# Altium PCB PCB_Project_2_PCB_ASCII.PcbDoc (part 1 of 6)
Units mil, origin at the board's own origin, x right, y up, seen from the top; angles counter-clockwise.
Board outline 3900 x 7800 mil, 6 copper layers (Top Layer, GND 1, Signal, Power, GND 2, Bottom Layer), stack 62.1 mil thick; 636 components, 334 nets, 1830 pads, 1401 vias.
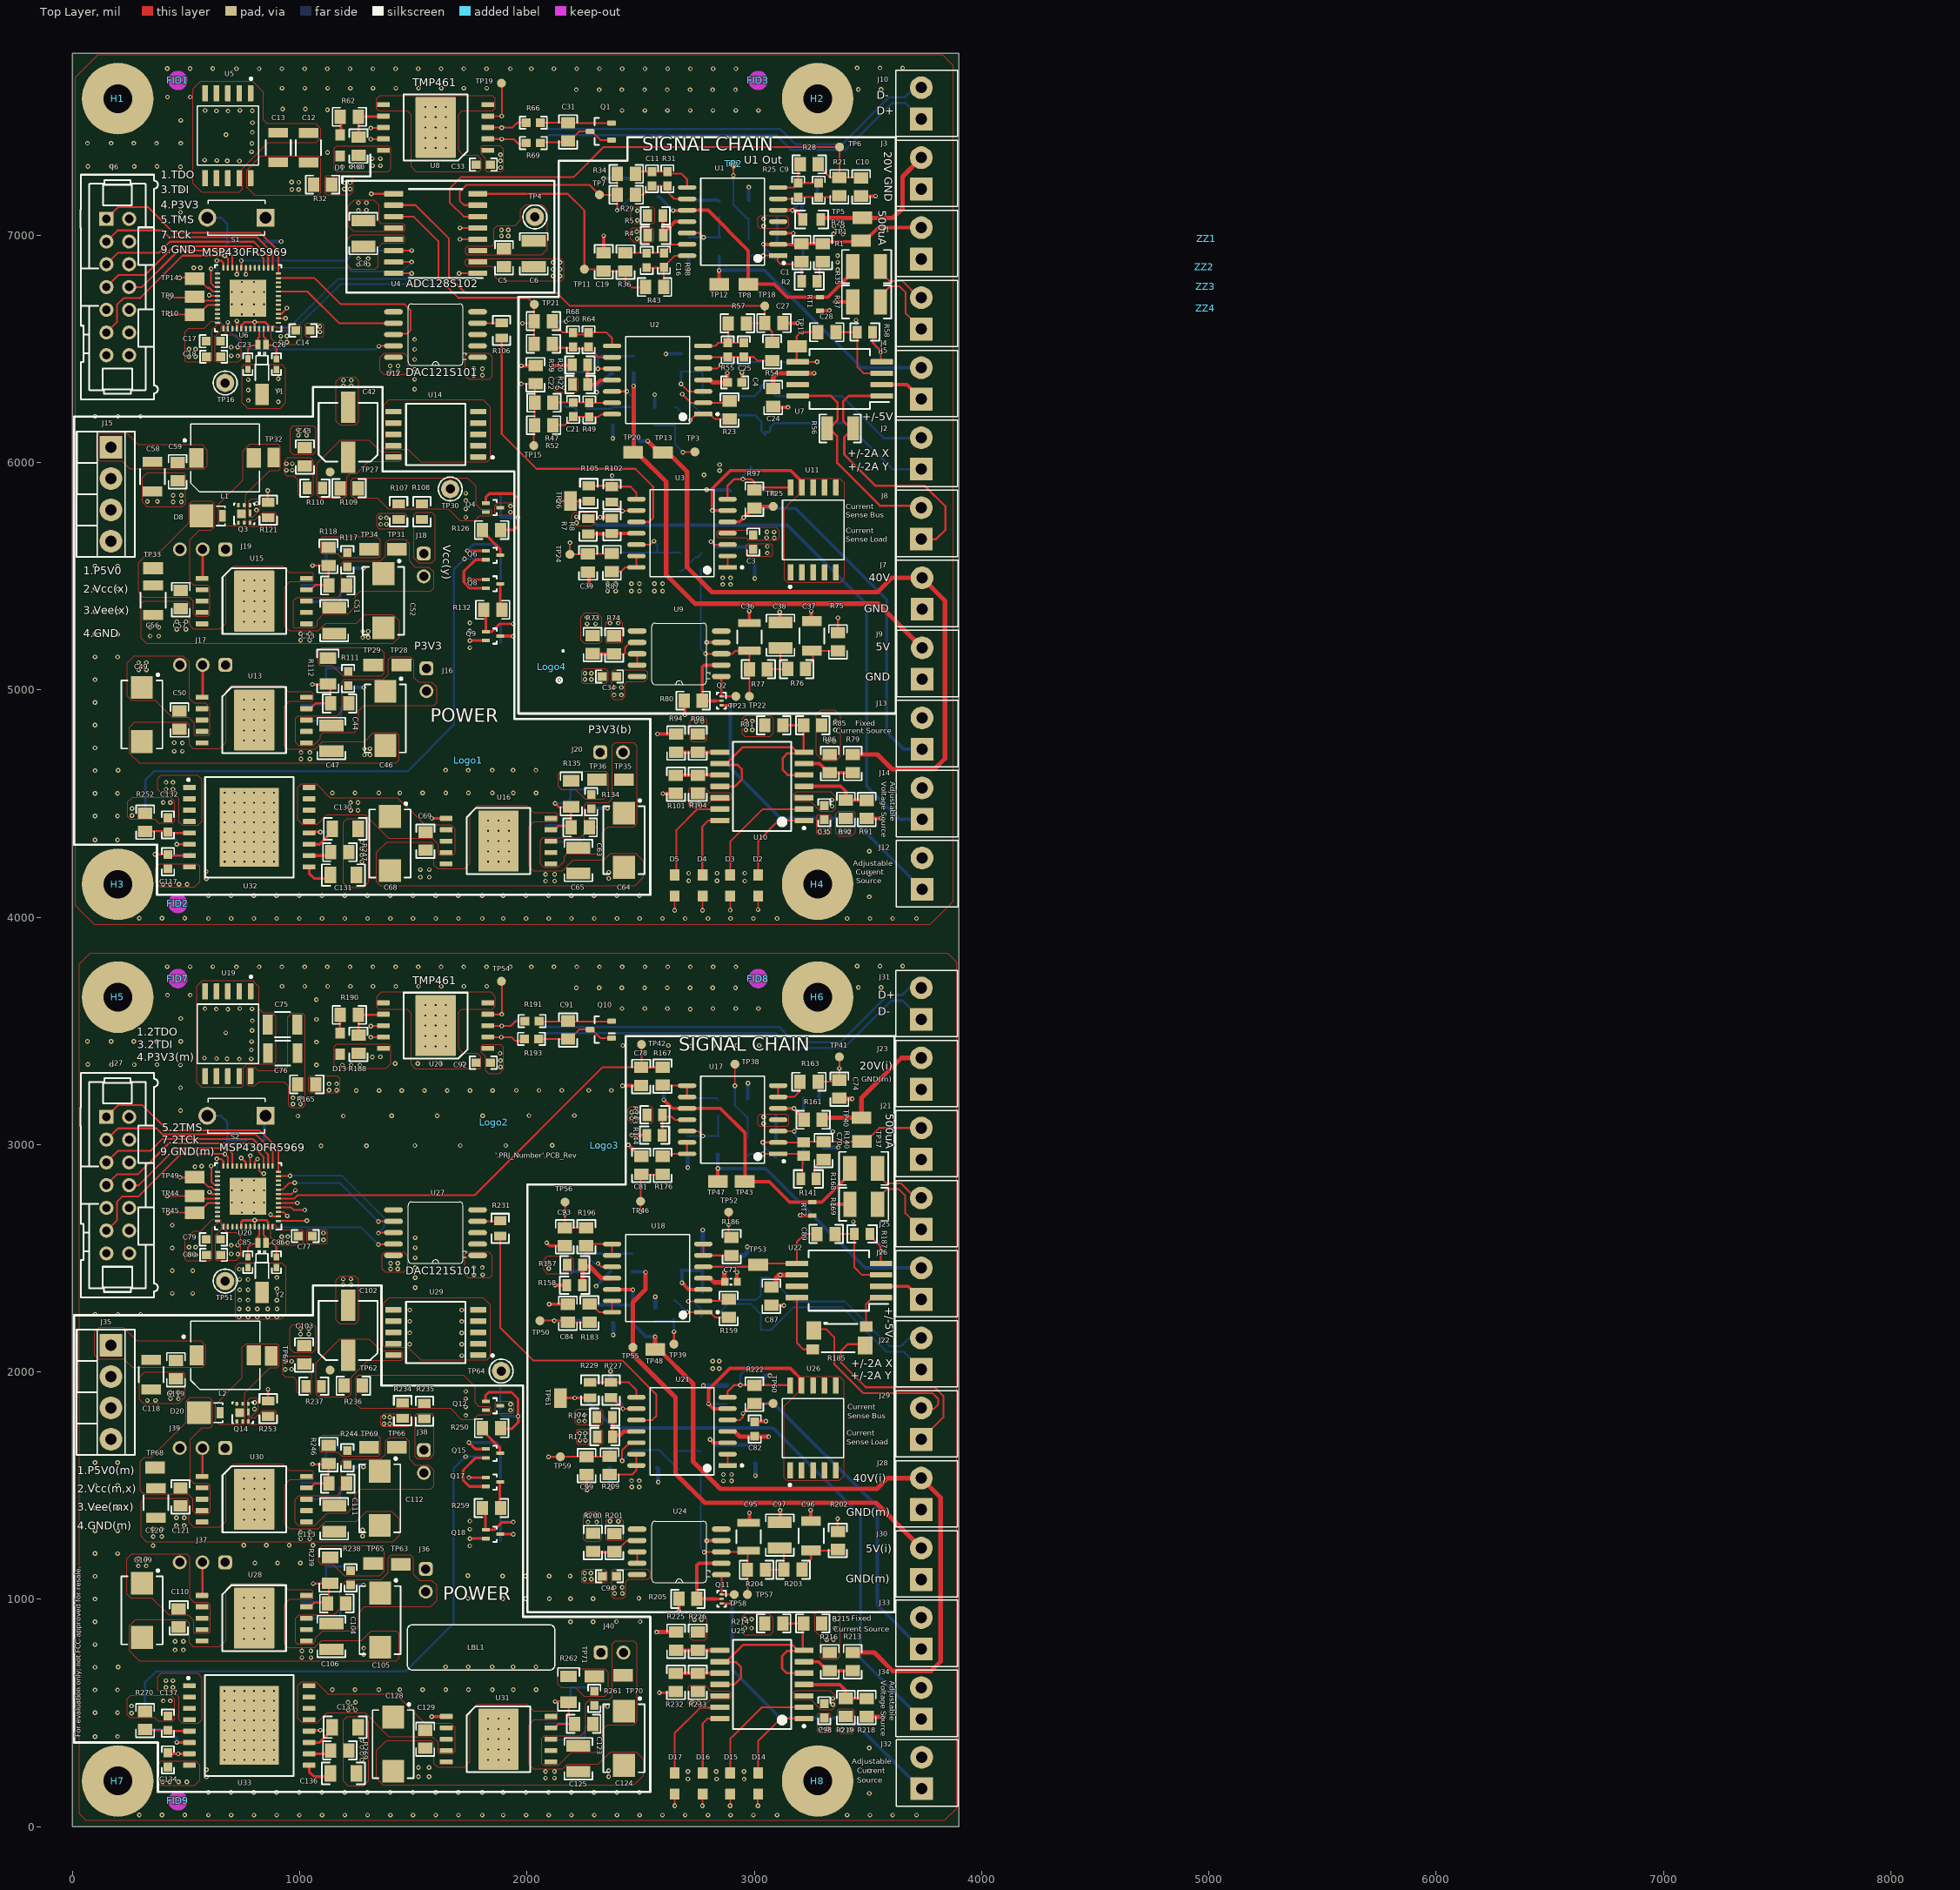
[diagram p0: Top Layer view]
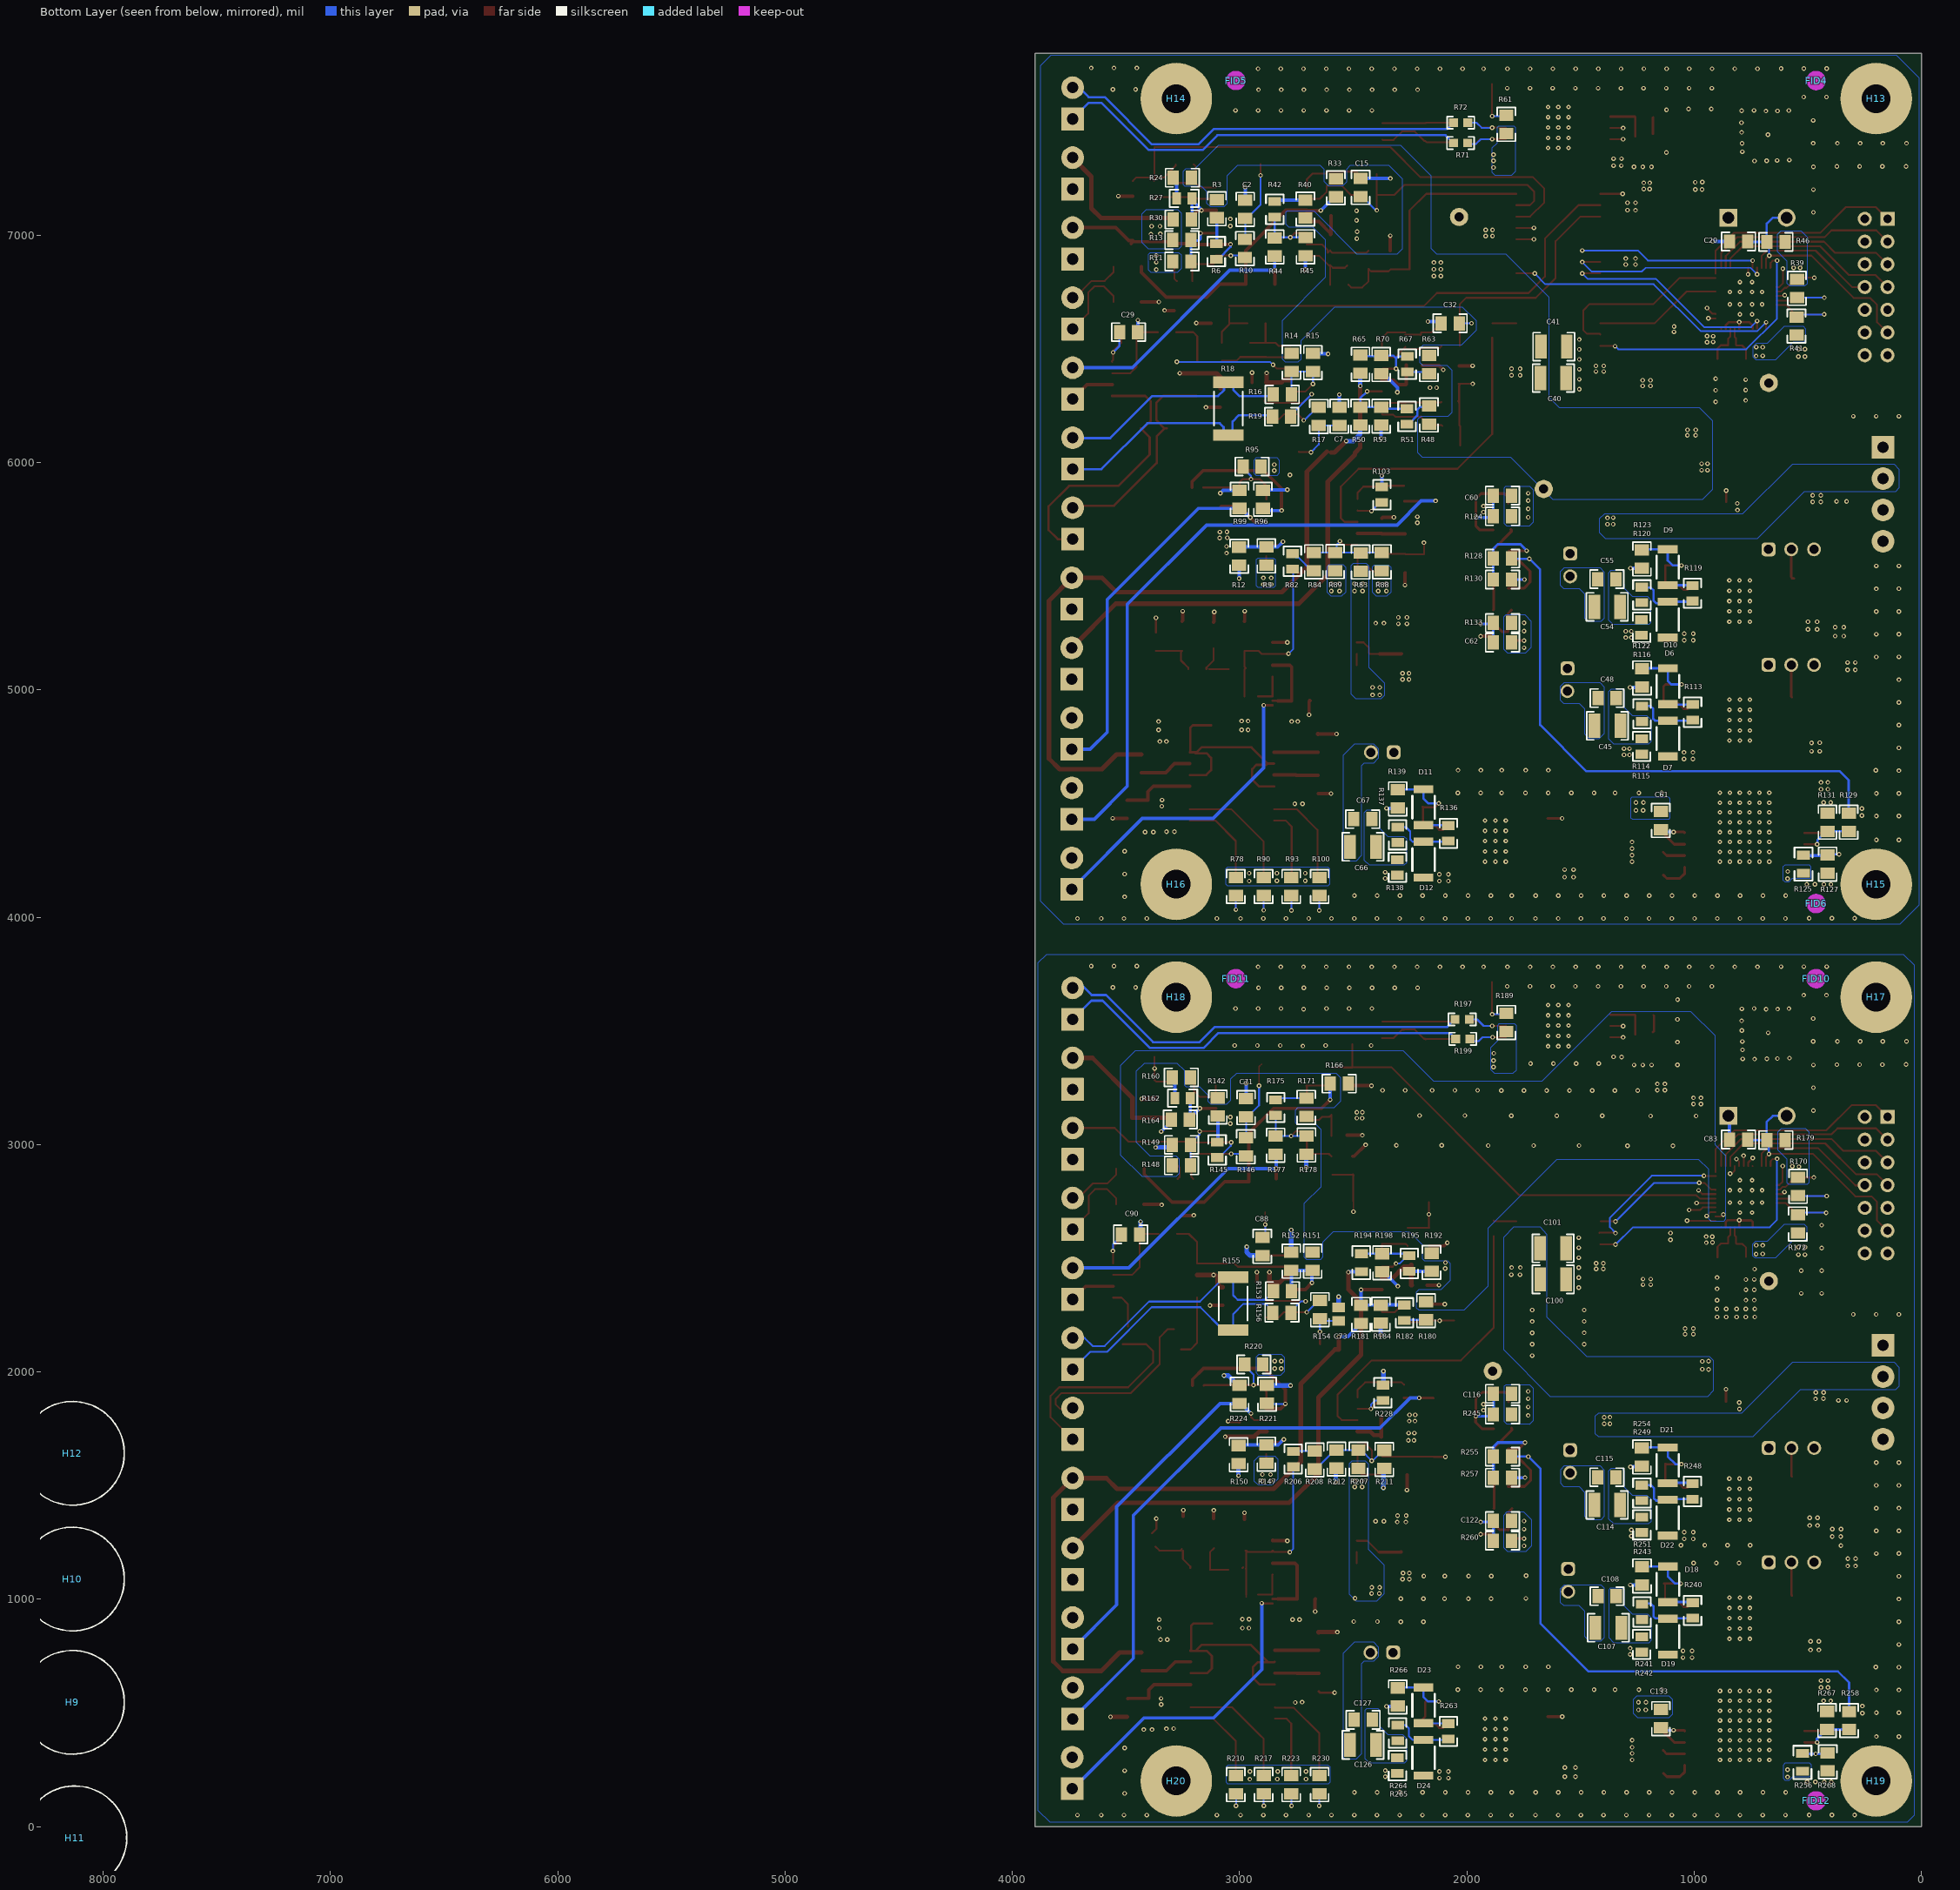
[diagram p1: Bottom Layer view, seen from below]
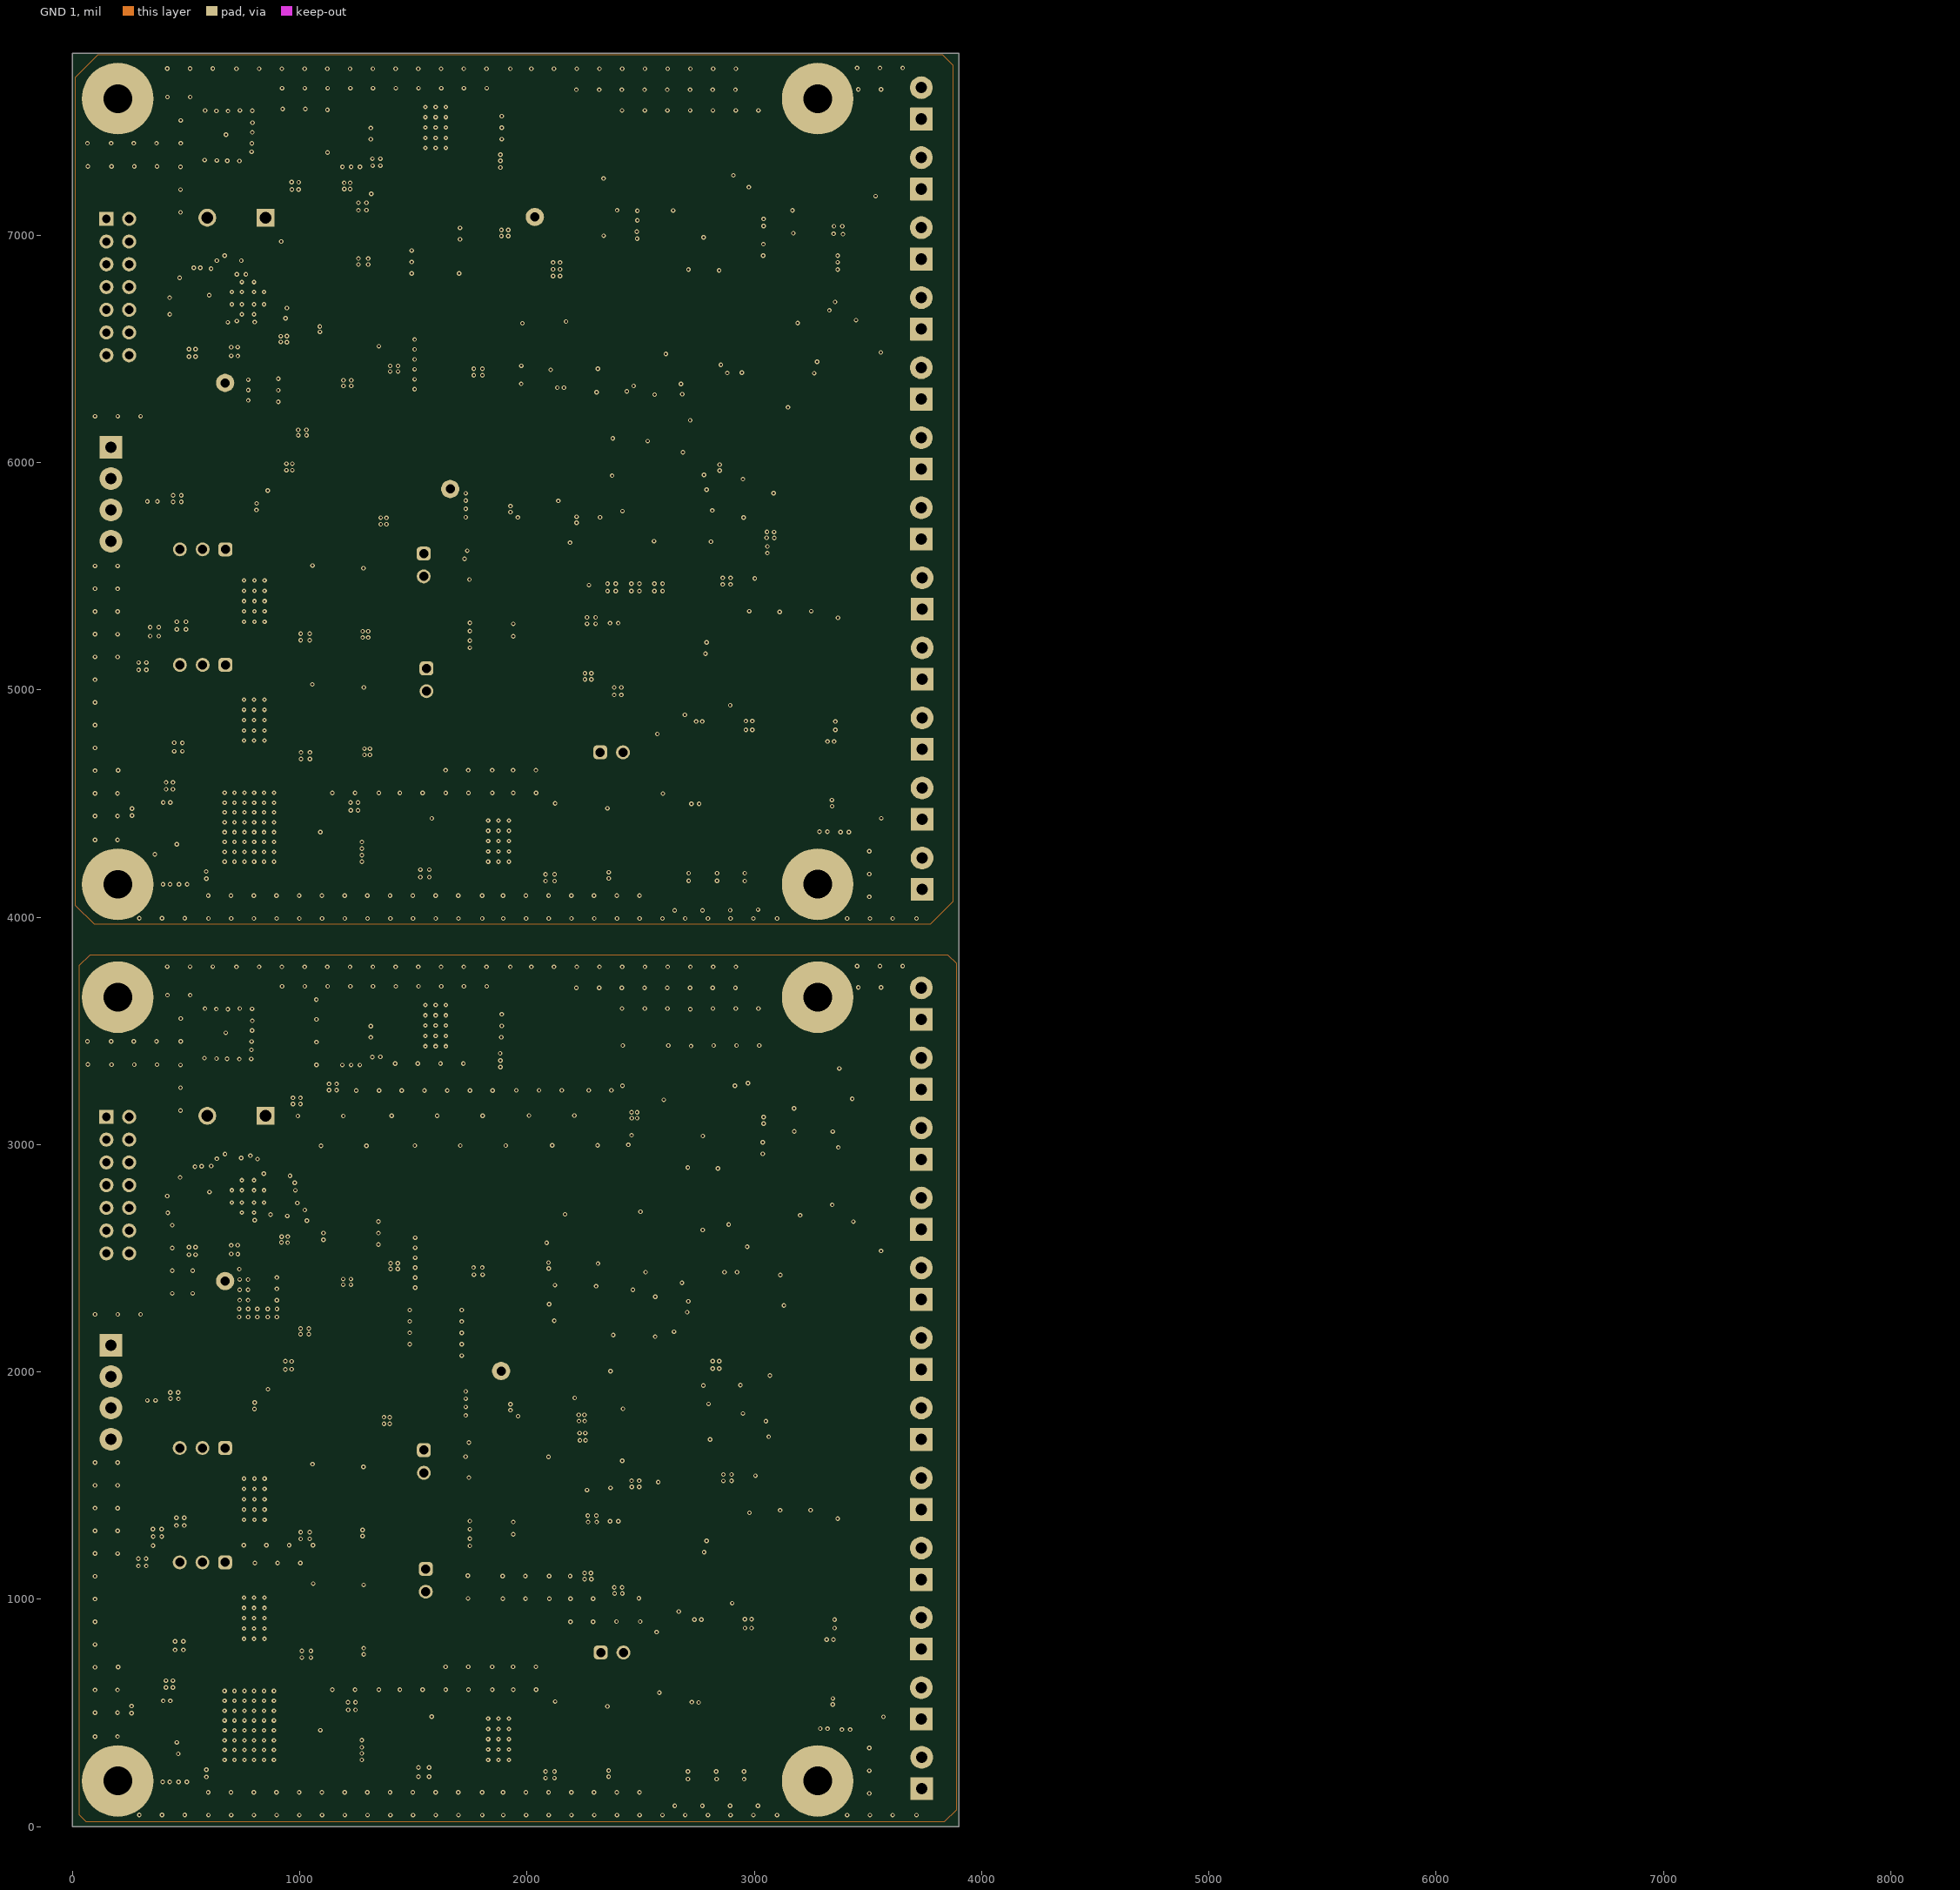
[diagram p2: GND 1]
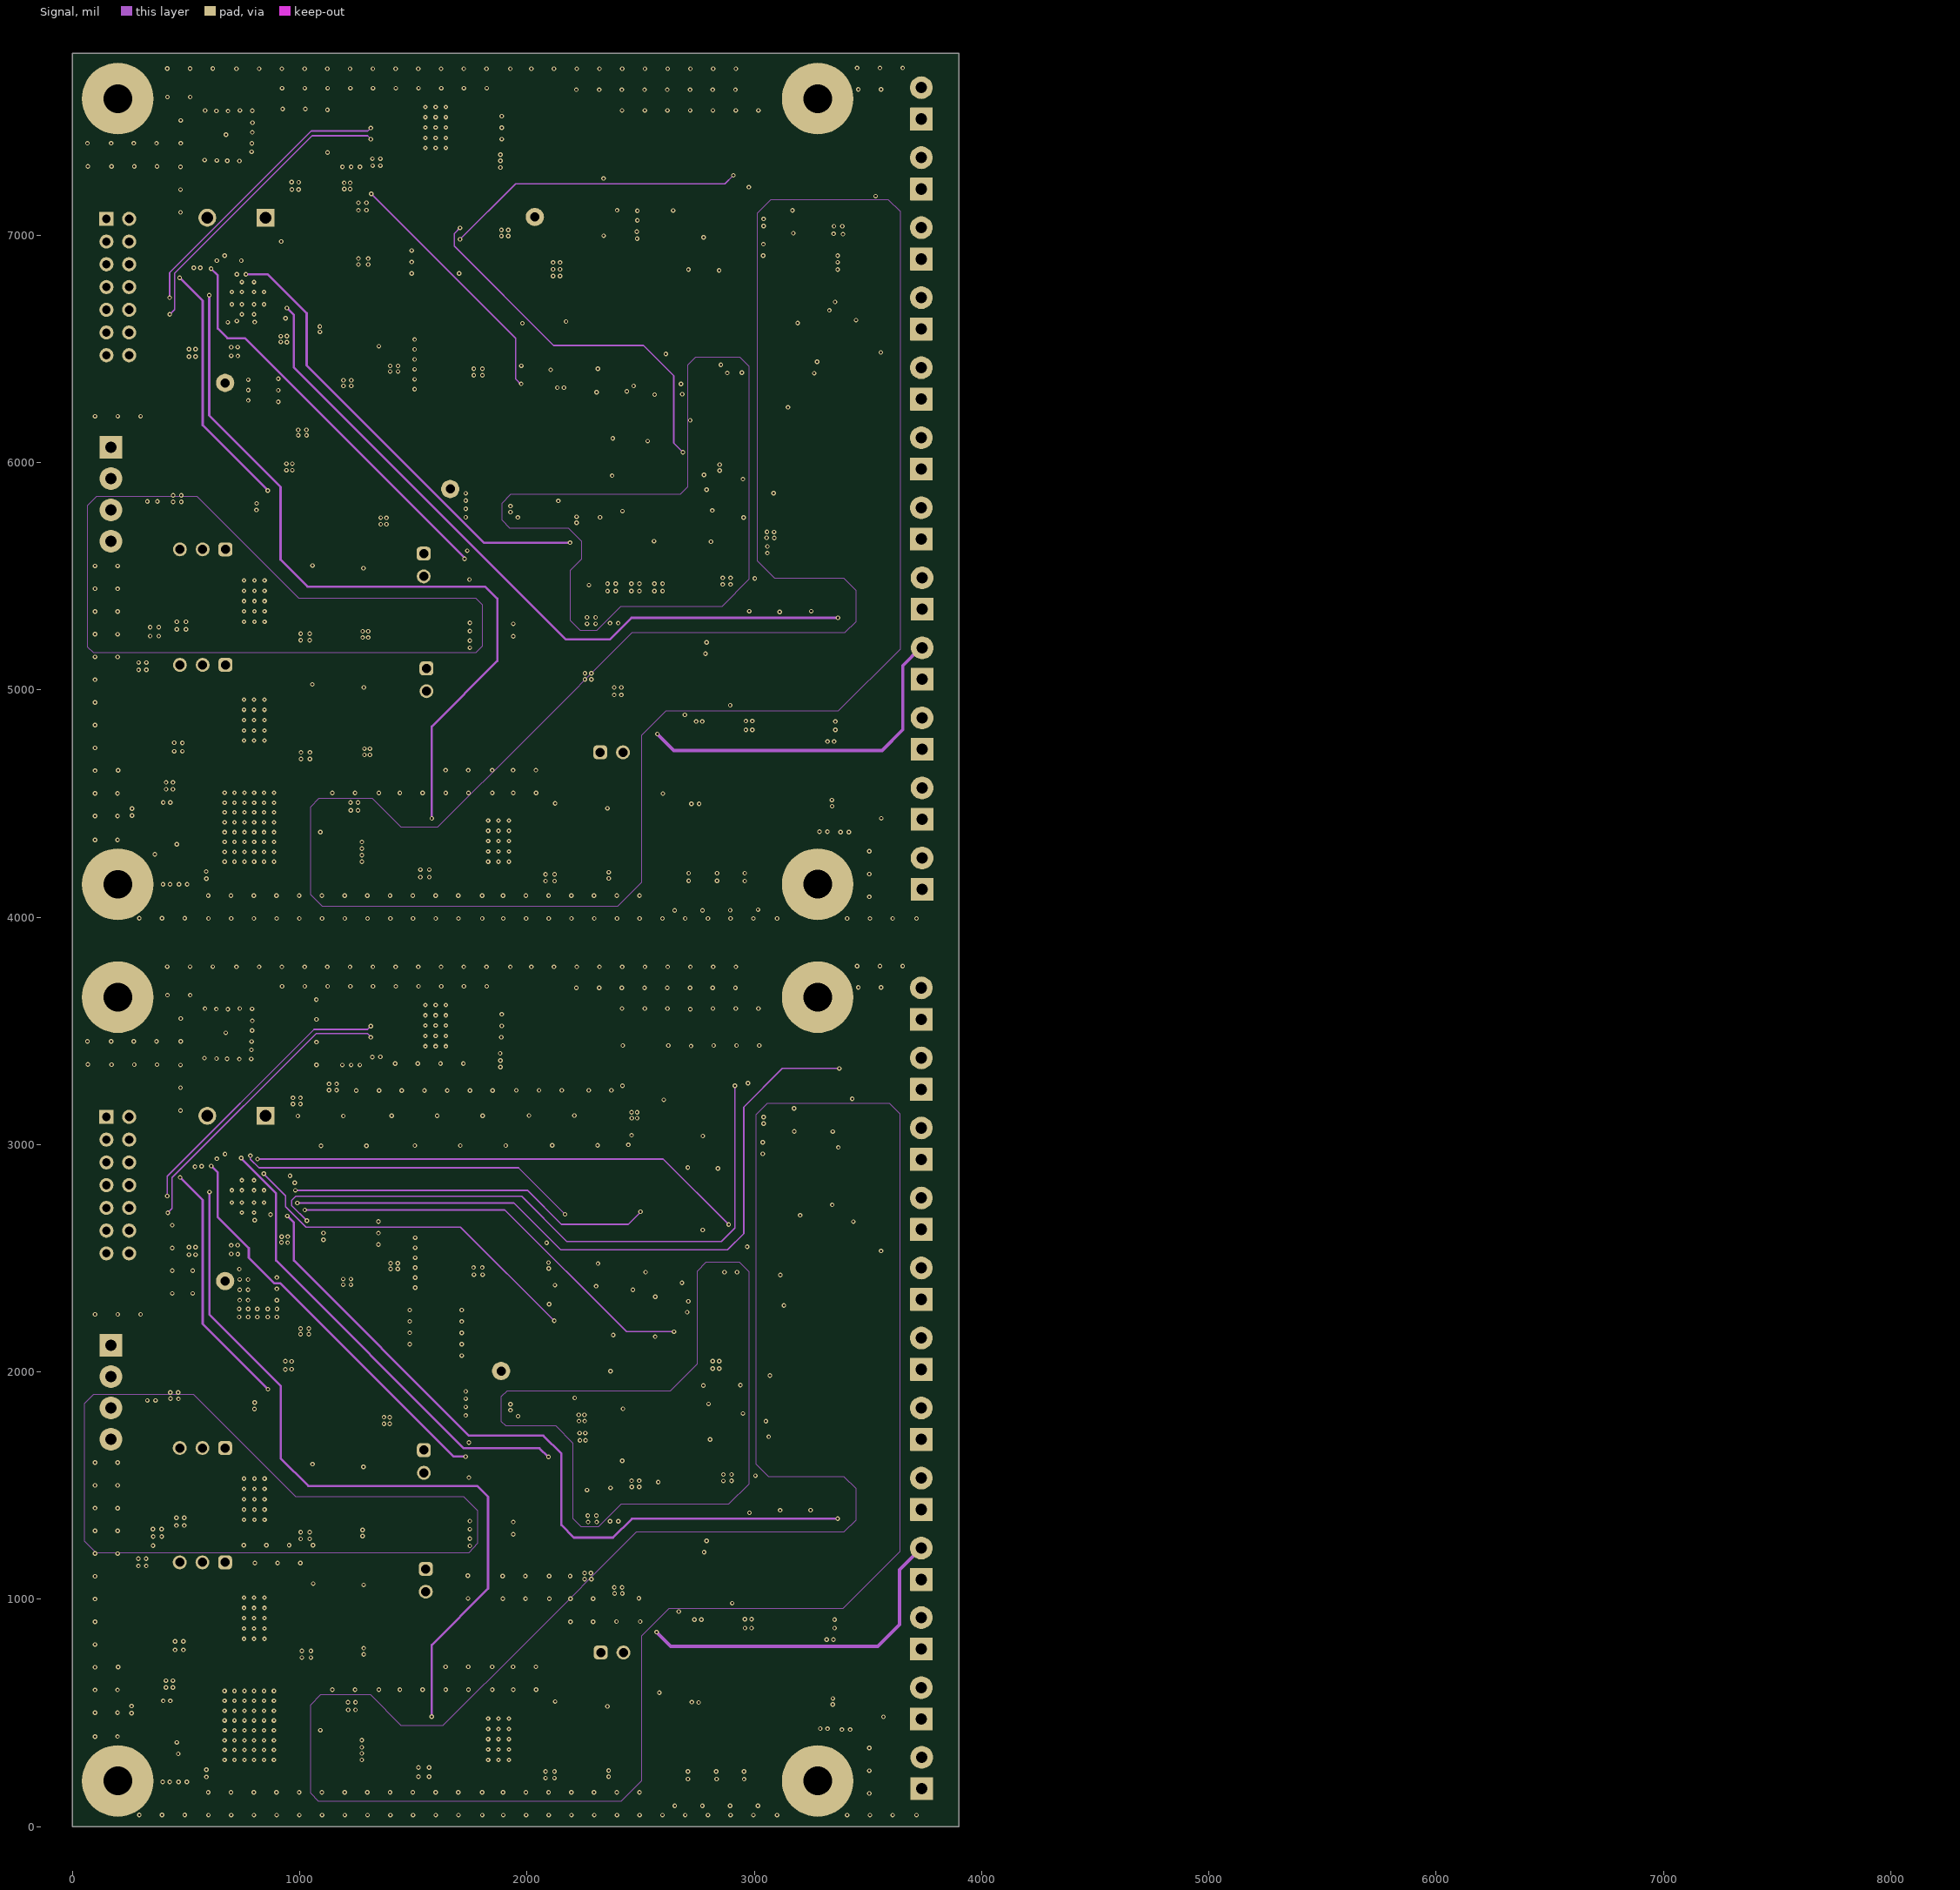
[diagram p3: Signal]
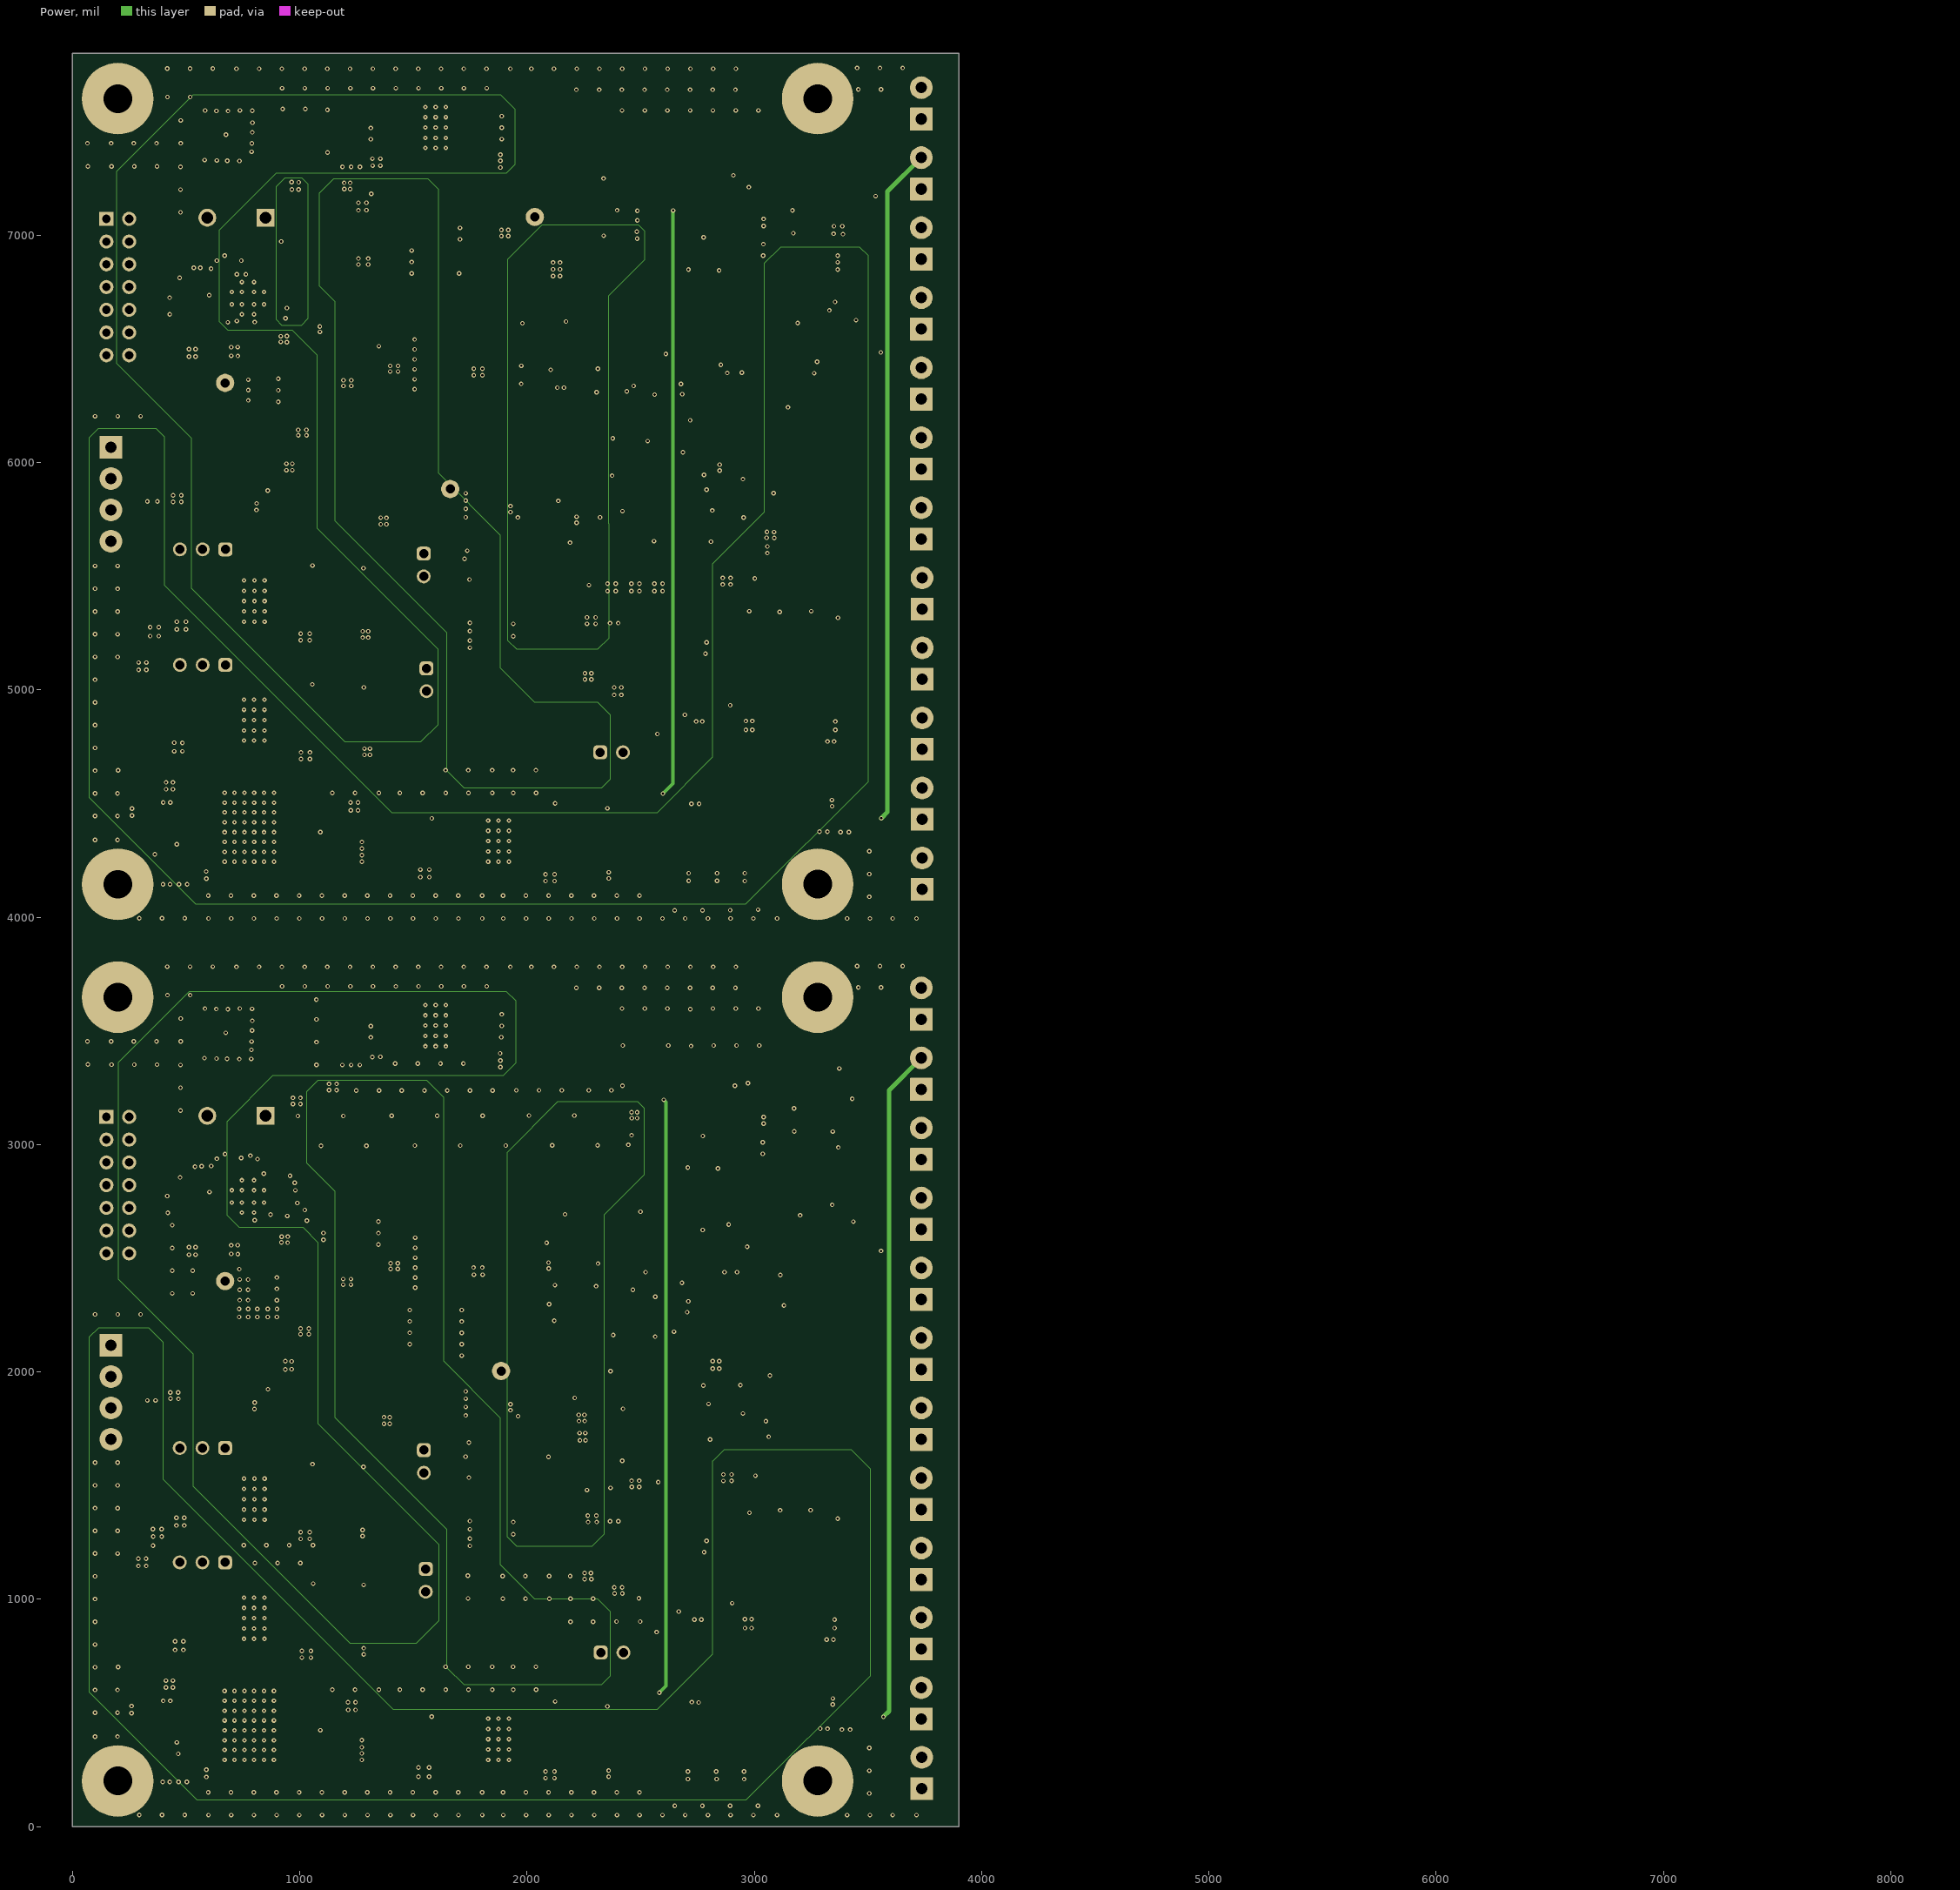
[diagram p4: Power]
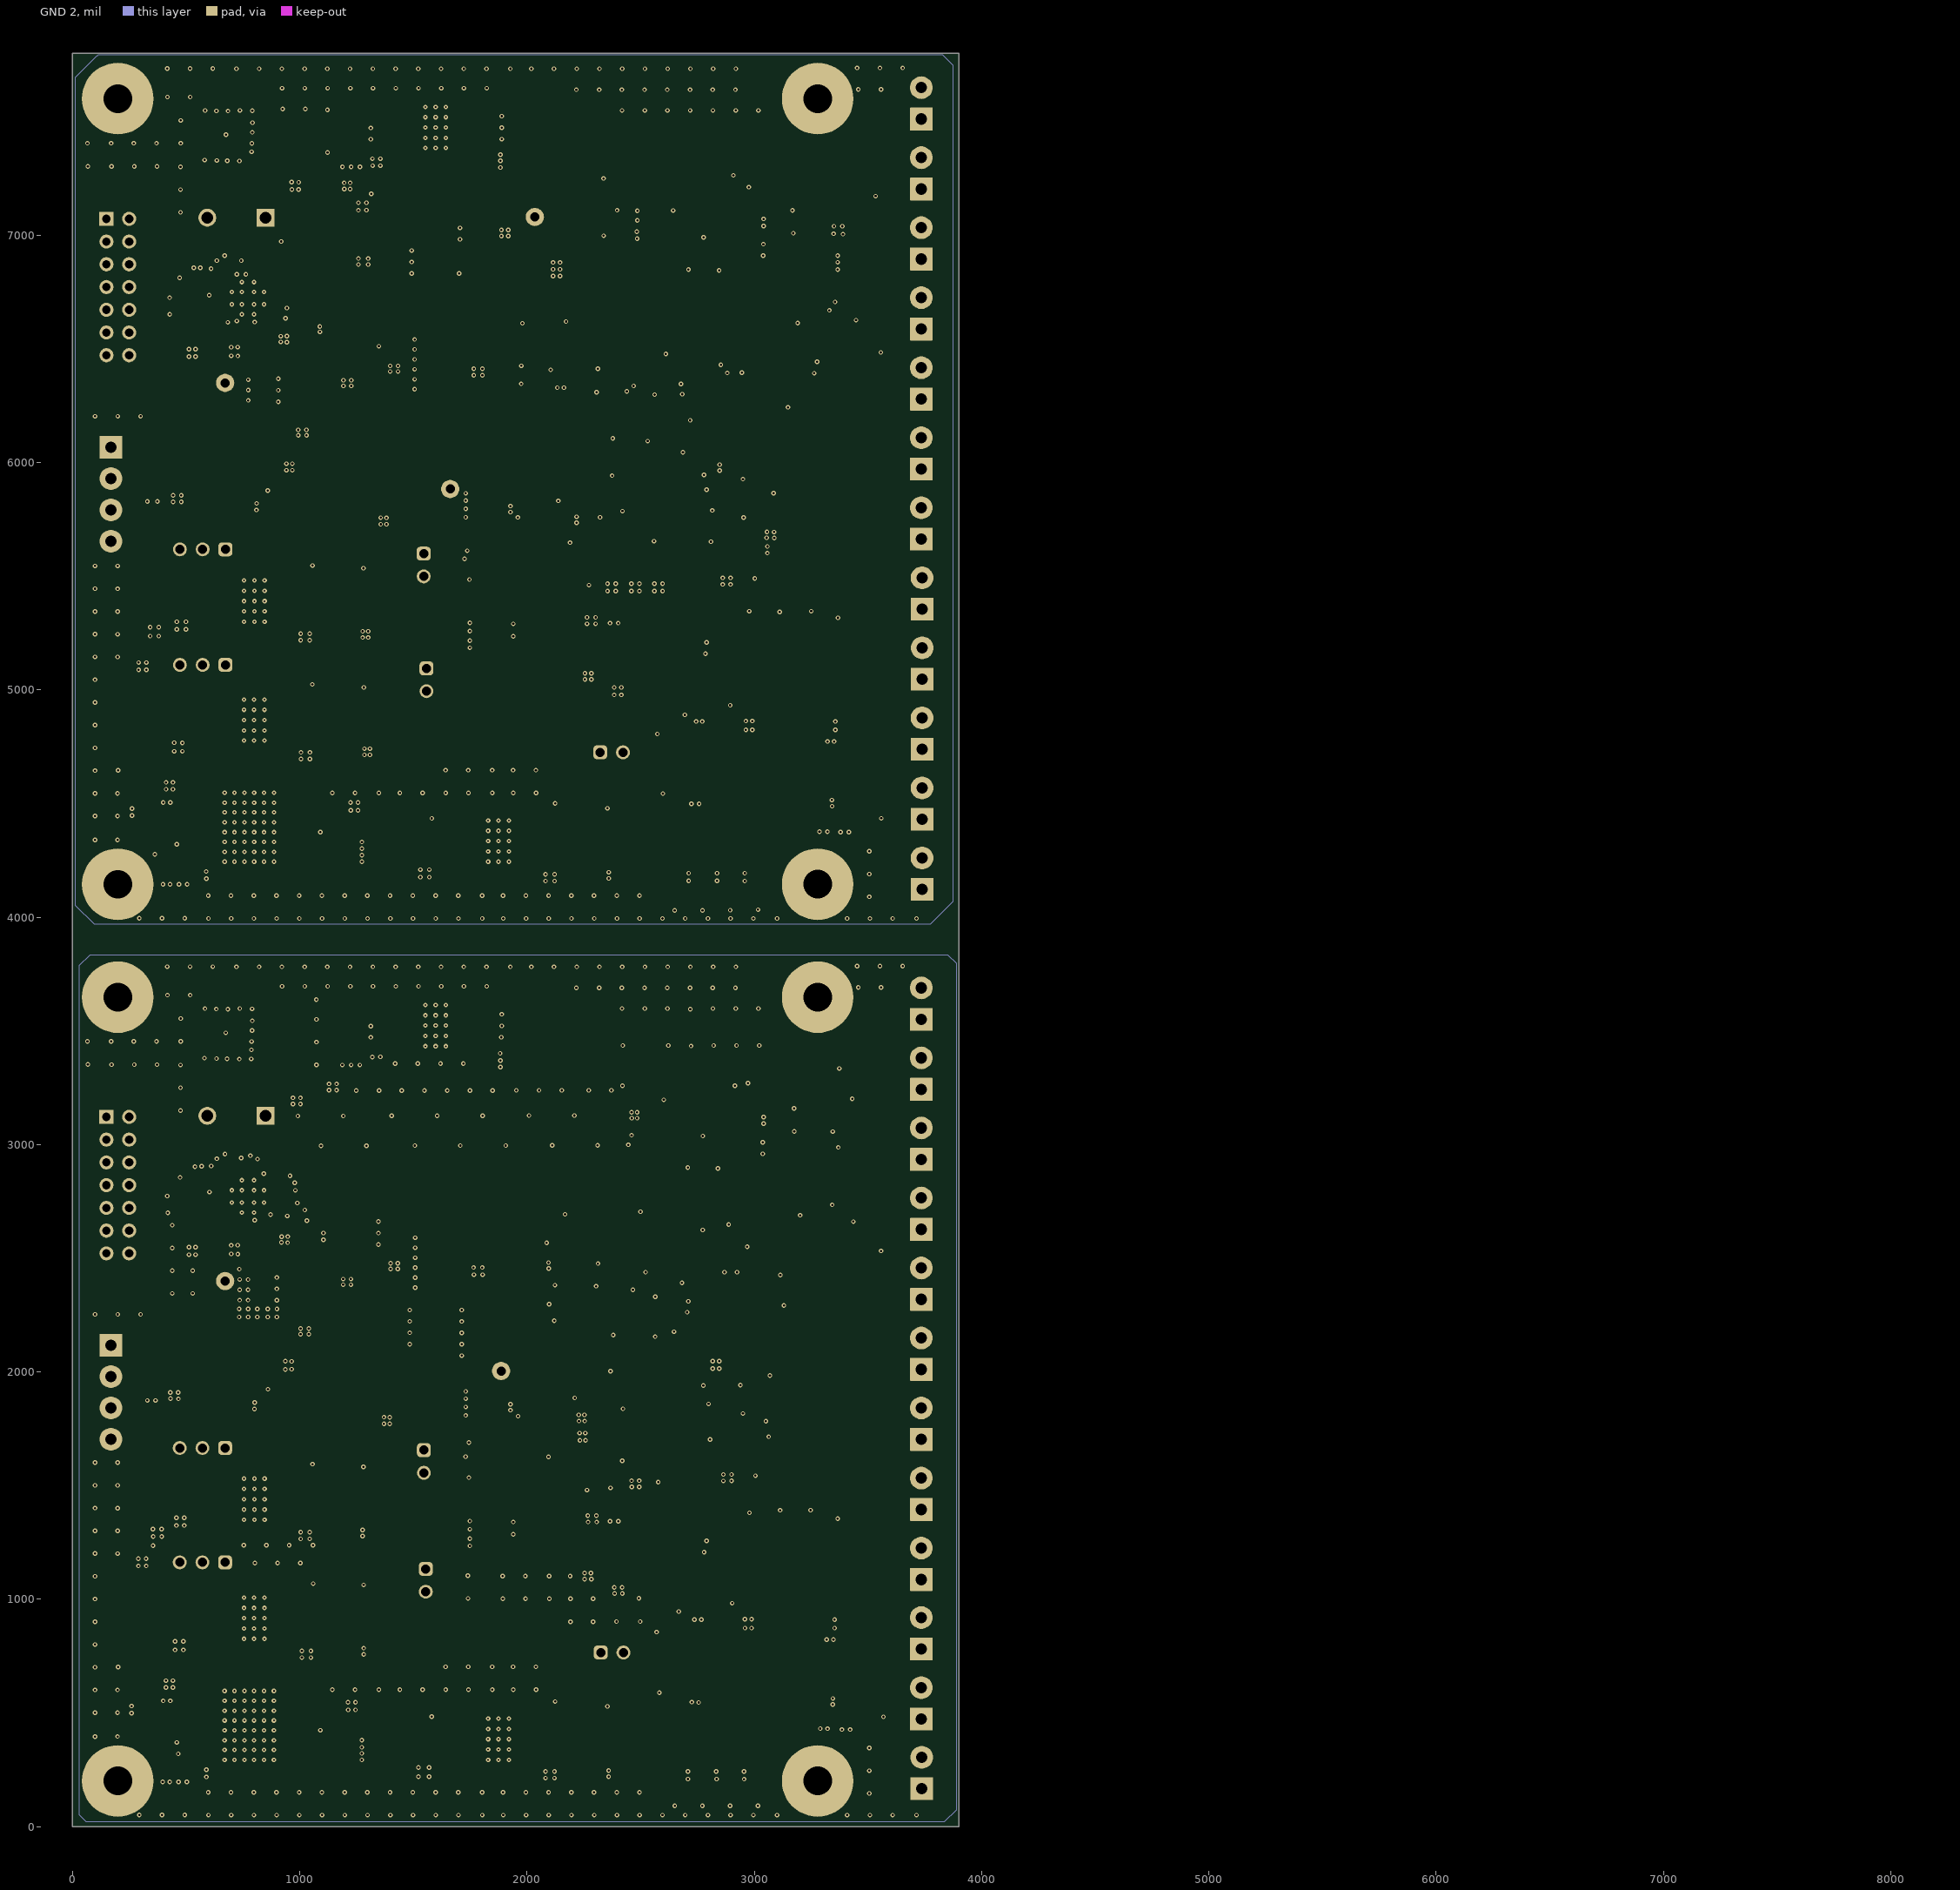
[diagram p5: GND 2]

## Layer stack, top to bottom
Top Solder: solder mask 0.4, Solder Resist, Dk 3.5
Top Layer: signal copper 1.4
Dielectric 1: prepreg 5, PP-006, Dk 4.1
GND 1: signal copper 1.378
Dielectric 3: prepreg 6, PP-006, Dk 4.1
Signal: signal copper 1.378
Dielectric1: core 31.788, FR-4, Dk 4.8
Power: signal copper 1.378
Dielectric 4: prepreg 6, PP-006, Dk 4.1
GND 2: signal copper 1.378
Dielectric 2: prepreg 5, PP-006, Dk 4.1
Bottom Layer: signal copper 1.4
Bottom Solder: solder mask 0.4, Solder Resist, Dk 3.5

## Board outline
0,0 0,3950 0,7800 3900,7800 3900,3950 3900,3850 3900,0

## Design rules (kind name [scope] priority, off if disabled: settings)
AcuteAngle [All] p0: scope1count=1 scope1_0_kind=Board scope1_0_value=Board scope2count=1 scope2_0_kind=Board scope2_0_value=Board commentlength=0 minimum=4.50000000000000E+0001
AcuteAngle [All] p1: minimum=4.50000000000000E+0001 checktracksonly=FALSE
AssemblyTestPointUsage [All] p0: scope1count=1 scope1_0_kind=Board scope1_0_value=Board scope2count=1 scope2_0_kind=Board scope2_0_value=Board commentlength=0
AssemblyTestPointUsage [All] p1: valid=2
AssemblyTestpoint [All] p0: scope1count=1 scope1_0_kind=Board scope1_0_value=Board scope2count=1 scope2_0_kind=Board scope2_0_value=Board commentlength=0
BoardOutlineClearance [All] p0 off: scope1count=1 scope1_0_kind=Board scope1_0_value=Board scope2count=1 scope2_0_kind=Board scope2_0_value=Board commentlength=172 gap=75 // Protel DXP Scope 1 Expression Was: OnCopper and Not InComponentClass('Logo') and not InComponentClass('FiducialMark') and not InRegion(1000,500,4000,800) and not InPoly
BoardOutlineClearance BoardOutlineClearance_Poly [All] p0 off: scope1count=1 scope1_0_kind=Board scope1_0_value=Board scope2count=1 scope2_0_kind=Board scope2_0_value=Board commentlength=58 gap=25 // Protel DXP Scope 1 Expression Was: OnCopper and IsPoly
BoardOutlineClearance BoardOutlineClearance_MountingHoles [All] p0 off: scope1count=1 scope1_0_kind=Board scope1_0_value=Board scope2count=1 scope2_0_kind=Board scope2_0_value=Board commentlength=86 gap=39.37 // Protel DXP Scope 1 Expression Was: OnCopper and InComponentClass('Mounting Holes')
BoardOutlineClearance BoardOutlineClearance_MountingHoles [OnCopper and InComponentClass('Mounting Holes')] p1: gap=39.37 ignorepadtopadclearanceinfootprint=FALSE
BoardOutlineClearance BoardOutlineClearance_Poly [OnCopper and IsPoly] p2: gap=25 ignorepadtopadclearanceinfootprint=FALSE
BoardOutlineClearance [OnCopper and Not InComponentClass('Logo') and not InComponentClass('FiducialMark') and not InRegion(1000,500,4000,800) and not InPoly] p3: gap=75 ignorepadtopadclearanceinfootprint=FALSE except(40: Via-OutlineEdge; 50: Track-OutlineEdge Track-CavityEdge Track-CutoutEdge Track-SplitBarrior Track-SplitContinuation)
Clearance [All] p0: scope1count=1 scope1_0_kind=Board scope1_0_value=Board scope2count=1 scope2_0_kind=Board scope2_0_value=Board commentlength=0 gap=8
Clearance Clearance_FiducialMark [All] p0 off: scope1count=1 scope1_0_kind=Board scope1_0_value=Board scope2count=1 scope2_0_kind=Board scope2_0_value=Board commentlength=81 gap=0 // Protel DXP Scope 2 Expression Was: IsPad and InComponentClass('FiducialMark')
Clearance Clearance_Poly [All] p0 off: scope1count=1 scope1_0_kind=Board scope1_0_value=Board scope2count=1 scope2_0_kind=Board scope2_0_value=Board commentlength=48 gap=25 // Protel DXP Scope 1 Expression Was: InPolygon
Clearance Clearance_Keepouts [All] p0 off: scope1count=1 scope1_0_kind=Board scope1_0_value=Board scope2count=1 scope2_0_kind=Board scope2_0_value=Board commentlength=99 gap=0 // Protel DXP Scope 2 Expression Was: ((IsTrack Or IsArc) And Not InPoly) And IsFree and IsKeepOut
Clearance Clearance_FiducialMark [IsKeepOut and InComponentClass('FiducialMark') vs IsPad and InComponentClass('FiducialMark')] p1: gap=0 ignorepadtopadclearanceinfootprint=FALSE
Clearance [All] p2: gap=8 ignorepadtopadclearanceinfootprint=TRUE except(15: Fill-Fill Fill-Poly Fill-Region Poly-Poly Poly-Region Region-Region)
Clearance Clearance_Keepouts [((IsTrack Or IsArc) And Not InPoly) And IsFree and IsKeepOut vs ((IsTrack Or IsArc) And Not InPoly) And IsFree and IsKeepOut] p3: gap=0 ignorepadtopadclearanceinfootprint=FALSE
Clearance Clearance_Poly [InPolygon] p4: gap=25 ignorepadtopadclearanceinfootprint=TRUE
ComponentClearance [All] p0: scope1count=1 scope1_0_kind=Board scope1_0_value=Board scope2count=1 scope2_0_kind=Board scope2_0_value=Board commentlength=0 gap=9.84 collisioncheckmode=3
ComponentClearance ComponentClearance_THtoTH [All] p0 off: scope1count=1 scope1_0_kind=Board scope1_0_value=Board scope2count=1 scope2_0_kind=Board scope2_0_value=Board commentlength=54 gap=9.84 collisioncheckmode=3 // Protel DXP Scope 2 Expression Was: IsThruComponent
ComponentClearance ComponentClearance_THtoSMT [All] p0 off: scope1count=1 scope1_0_kind=Board scope1_0_value=Board scope2count=1 scope2_0_kind=Board scope2_0_value=Board commentlength=53 gap=9.84 collisioncheckmode=3 // Protel DXP Scope 2 Expression Was: IsSMTComponent
ComponentClearance ComponentClearance_SmallPassives [All] p0 off: scope1count=1 scope1_0_kind=Board scope1_0_value=Board scope2count=1 scope2_0_kind=Board scope2_0_value=Board commentlength=508 gap=14.96 collisioncheckmode=3 // Protel DXP Scope 2 Expression Was: HasFootprint('0201*') or HasFootprint('0402*') or HasFootprint('0508') or HasFootprint('0603*') or HasFootprint('0612') or HasFootprint('0805*') or HasFootprint('0815*') or HasFootprint('0830*') or HasFootprint('1206*') or HasFootprint('1210*') or HasFootprint('1808*') or HasFootprint('1812*') or HasFootprint('1825*') or HasFootprint('2010*') or HasFootprint('2220*') or HasFootprint('2225*') or HasFootprint('2512*') or HasFootprint('2728*') or HasFootprint('3518*')
ComponentClearance ComponentClearance_MountingHoles [All] p0: scope1count=1 scope1_0_kind=ComponentClass scope1_0_value="Mounting Holes" scope2count=1 scope2_0_kind=Board scope2_0_value=Board commentlength=0 gap=39.37 collisioncheckmode=3
ComponentClearance ComponentClearance_ScrewToNut [All] p0 off: scope1count=1 scope1_0_kind=Board scope1_0_value=Board scope2count=1 scope2_0_kind=Board scope2_0_value=Board commentlength=71 gap=5 collisioncheckmode=3 // Protel DXP Scope 2 Expression Was: (HasFootprint('Keystone_1902C'))
ComponentClearance ComponentClearance_Logo [All] p0: scope1count=1 scope1_0_kind=ComponentClass scope1_0_value=Logo scope2count=1 scope2_0_kind=Board scope2_0_value=Board commentlength=0 gap=50 collisioncheckmode=3
ComponentClearance ComponentClearance_Shunt [All] p0: scope1count=1 scope1_0_kind=ComponentClass scope1_0_value=Header scope2count=1 scope2_0_kind=ComponentClass scope2_0_value=Shunt commentlength=0 gap=0 collisioncheckmode=3
ComponentClearance ComponentClearance_MountingHoles_FiducialMarks [All] p0: scope1count=1 scope1_0_kind=ComponentClass scope1_0_value="Mounting Holes" scope2count=1 scope2_0_kind=ComponentClass scope2_0_value=FiducialMark commentlength=0 gap=50 collisioncheckmode=3
ComponentClearance ComponentClearance_MountingHoles_FiducialMarks [InComponentClass('Mounting Holes') vs InComponentClass('FiducialMark')] p1: gap=50 collisioncheckmode=3 verticalgap=10 showdistances=FALSE
ComponentClearance ComponentClearance_Shunt [InComponentClass('Header') vs InComponentClass('Shunt')] p2: gap=0 collisioncheckmode=3 verticalgap=0 showdistances=FALSE
ComponentClearance ComponentClearance_Logo [InComponentClass('Logo')] p3: gap=50 collisioncheckmode=3 verticalgap=10 showdistances=FALSE
ComponentClearance ComponentClearance_ScrewToNut [(HasFootprint('NY PMS 440 0025 PH')) vs (HasFootprint('Keystone_1902C'))] p4: gap=5 collisioncheckmode=3 verticalgap=10 showdistances=FALSE
ComponentClearance ComponentClearance_MountingHoles [InComponentClass('Mounting Holes')] p5: gap=39.37 collisioncheckmode=3 verticalgap=100000 showdistances=FALSE
ComponentClearance ComponentClearance_SmallPassives [HasFootprint('0201*') or HasFootprint('0402*') or HasFootprint('0508') or HasFootprint('0603*') or HasFootprint('0612') or HasFootprint('0805*') or HasFootprint('0815*') or HasFootprint('0830*') or HasFootprint('1206*') or HasFootprint('1210*') or HasFootprint('1808*') or HasFootprint('1812*') or HasFootprint('1825*') or HasFootprint('2010*') or HasFootprint('2220*') or HasFootprint('2225*') or HasFootprint('2512*') or HasFootprint('2728*') or HasFootprint('3518*') vs HasFootprint('0201*') or HasFootprint('0402*') or HasFootprint('0508') or HasFootprint('0603*') or HasFootprint('0612') or HasFootprint('0805*') or HasFootprint('0815*') or HasFootprint('0830*') or HasFootprint('1206*') or HasFootprint('1210*') or HasFootprint('1808*') or HasFootprint('1812*') or HasFootprint('1825*') or HasFootprint('2010*') or HasFootprint('2220*') or HasFootprint('2225*') or HasFootprint('2512*') or HasFootprint('2728*') or HasFootprint('3518*')] p6: gap=14.96 collisioncheckmode=3 verticalgap=10 showdistances=FALSE
ComponentClearance ComponentClearance_THtoSMT [IsThruComponent vs IsSMTComponent] p7: gap=9.84 collisioncheckmode=3 verticalgap=30 showdistances=FALSE
ComponentClearance ComponentClearance_THtoTH [IsThruComponent vs IsThruComponent] p8: gap=9.84 collisioncheckmode=3 verticalgap=30 showdistances=FALSE
ComponentClearance [All] p9: gap=9.84 collisioncheckmode=3 verticalgap=10 showdistances=FALSE
DiffPairsRouting [All] p0: scope1count=1 scope1_0_kind=Board scope1_0_value=Board scope2count=1 scope2_0_kind=Board scope2_0_value=Board commentlength=0
DiffPairsRouting [All] p1: maxlimit=100 minlimit=10 mostfreqgap=10 toplayer_minwidth=15 toplayer_maxwidth=15 toplayer_prefwidth=15 midlayer1_minwidth=15 midlayer1_maxwidth=15 midlayer1_prefwidth=15 midlayer2_minwidth=15 midlayer2_maxwidth=15 midlayer2_prefwidth=15 midlayer3_minwidth=15 midlayer3_maxwidth=15 midlayer3_prefwidth=15 midlayer4_minwidth=15 midlayer4_maxwidth=15 midlayer4_prefwidth=15 bottomlayer_minwidth=15 bottomlayer_maxwidth=15 bottomlayer_prefwidth=15 maxuncoupledlength=1000
FabricationTestPointUsage TestPointUsage [All] p0: scope1count=1 scope1_0_kind=Board scope1_0_value=Board scope2count=1 scope2_0_kind=Board scope2_0_value=Board commentlength=0 valid=2 allowmultiple=FALSE
FabricationTestPointUsage TestPointUsage [All] p1: valid=2 allowmultiple=FALSE
FabricationTestpoint Testpoint [All] p0: scope1count=1 scope1_0_kind=Board scope1_0_value=Board scope2count=1 scope2_0_kind=Board scope2_0_value=Board commentlength=0 side=3 testpointundercomponent=TRUE minsize=40 maxsize=100 preferedsize=60 minholesize=0 maxholesize=40 preferedholesize=32 testpointgrid=1
FabricationTestpoint Testpoint [All] p1: side=3 testpointundercomponent=TRUE minsize=40 maxsize=100 preferedsize=60 minholesize=0 maxholesize=40 preferedholesize=32 testpointgrid=1 allowsidetop=TRUE allowsidebottom=TRUE usegrid=TRUE gridtolerance=0.01
FanoutControl Fanout_Small [All] p0 off: scope1count=1 scope1_0_kind=Board scope1_0_value=Board scope2count=1 scope2_0_kind=Board scope2_0_value=Board commentlength=84 // Protel DXP Scope 1 Expression Was: (CompPinCount < 5)   Fanout_Small (Default Rule)
FanoutControl Fanout_Default [All] p0: scope1count=1 scope1_0_kind=Board scope1_0_value=Board scope2count=1 scope2_0_kind=Board scope2_0_value=Board commentlength=30 // Fanout_Default (Default Rule)
FanoutControl Fanout_SOIC [All] p0 off: scope1count=1 scope1_0_kind=Board scope1_0_value=Board scope2count=1 scope2_0_kind=Board scope2_0_value=Board commentlength=71 // Protel DXP Scope 1 Expression Was: IsSOIC   Fanout_SOIC (Default Rule)
FanoutControl Fanout_BGA [All] p0 off: scope1count=1 scope1_0_kind=Board scope1_0_value=Board scope2count=1 scope2_0_kind=Board scope2_0_value=Board commentlength=69 // Protel DXP Scope 1 Expression Was: IsBGA   Fanout_BGA (Default Rule)
FanoutControl Fanout_LCC [All] p0 off: scope1count=1 scope1_0_kind=Board scope1_0_value=Board scope2count=1 scope2_0_kind=Board scope2_0_value=Board commentlength=69 // Protel DXP Scope 1 Expression Was: IsLCC   Fanout_LCC (Default Rule)
FanoutControl Fanout_LCC [IsLCC] p1: bgadir=Out bgaviamode=Centered fanoutstyle=Auto fanoutdirection=Alternating viagrid=1 // Fanout_LCC (Default Rule)
FanoutControl Fanout_BGA [IsBGA] p2: bgadir=Out bgaviamode=Centered fanoutstyle=Auto fanoutdirection=Alternating viagrid=1 // Fanout_BGA (Default Rule)
FanoutControl Fanout_Default [All] p4: bgadir=Out bgaviamode=Centered fanoutstyle=Auto fanoutdirection=Alternating viagrid=1 // Fanout_Default (Default Rule)
FanoutControl Fanout_Small [(CompPinCount < 5)] p5: bgadir=Out bgaviamode=Centered fanoutstyle=Auto fanoutdirection=OutThenIn viagrid=1 // Fanout_Small (Default Rule)
Height [All] p0: scope1count=1 scope1_0_kind=Board scope1_0_value=Board scope2count=1 scope2_0_kind=Board scope2_0_value=Board commentlength=0
HoleSize [All] p0: scope1count=1 scope1_0_kind=Board scope1_0_value=Board scope2count=1 scope2_0_kind=Board scope2_0_value=Board commentlength=0 absolutevalues=TRUE maxlimit=251 minlimit=7.87 maxpercent=80.000 minpercent=20.000
HoleSize [All] p1: absolutevalues=TRUE maxlimit=251 minlimit=7.87 maxpercent=80.000 minpercent=20.000
HoleToHoleClearance [All] p0: scope1count=1 scope1_0_kind=Board scope1_0_value=Board scope2count=1 scope2_0_kind=Board scope2_0_value=Board commentlength=0
LayerPairs [All] p0: scope1count=1 scope1_0_kind=Board scope1_0_value=Board scope2count=1 scope2_0_kind=Board scope2_0_value=Board commentlength=0 enforce=TRUE
MinimumAnnularRing [All] p0: scope1count=1 scope1_0_kind=Board scope1_0_value=Board scope2count=1 scope2_0_kind=Board scope2_0_value=Board commentlength=0 minimumring=5
MinimumAnnularRing MinimumAnnularRing_ThermalPadVias [All] p0 off: scope1count=1 scope1_0_kind=Board scope1_0_value=Board scope2count=1 scope2_0_kind=Board scope2_0_value=Board commentlength=63 minimumring=5.91 // Protel DXP Scope 1 Expression Was: IsVia and InAnyComponent
MinimumAnnularRing MinimumAnnularRing_ThermalPadVias [IsVia and InAnyComponent] p1: minimumring=5.91
MinimumAnnularRing [All] p2: minimumring=5
MinimumSolderMaskSliver [All] p0: scope1count=1 scope1_0_kind=Board scope1_0_value=Board scope2count=1 scope2_0_kind=Board scope2_0_value=Board commentlength=0
MinimumSolderMaskSliver MinimumSolderMaskSliver_Logo [All] p0: scope1count=1 scope1_0_kind=ComponentClass scope1_0_value=Logo scope2count=1 scope2_0_kind=ComponentClass scope2_0_value=Logo commentlength=0
MinimumSolderMaskSliver MinimumSolderMaskSliver_Logo [InComponentClass('Logo') vs InComponentClass('Logo')] p1: minsoldermaskwidth=0.7
MinimumSolderMaskSliver [All] p2: minsoldermaskwidth=3.94
NetAntennae [All] p0: scope1count=1 scope1_0_kind=Board scope1_0_value=Board scope2count=1 scope2_0_kind=Board scope2_0_value=Board commentlength=0
PasteMaskExpansion [All] p0: scope1count=1 scope1_0_kind=Board scope1_0_value=Board scope2count=1 scope2_0_kind=Board scope2_0_value=Board commentlength=0 expansion=0
PlaneClearance [All] p0: scope1count=1 scope1_0_kind=Board scope1_0_value=Board scope2count=1 scope2_0_kind=Board scope2_0_value=Board commentlength=0 clearance=20
PlaneConnect [All] p0: scope1count=1 scope1_0_kind=Board scope1_0_value=Board scope2count=1 scope2_0_kind=Board scope2_0_value=Board commentlength=0 planeconnectstyle=Direct reliefexpansion=10 reliefentries=4 reliefconductorwidth=10 reliefairgap=10
PlaneConnect [All] p1: planeconnectstyle=Direct reliefexpansion=10 reliefentries=4 reliefconductorwidth=10 reliefairgap=10
PolygonConnect [All] p0: scope1count=1 scope1_0_kind=Board scope1_0_value=Board scope2count=1 scope2_0_kind=Board scope2_0_value=Board commentlength=0 connectstyle=Direct reliefconductorwidth=10 reliefentries=4 polygonreliefangle="90 Angle"
PolygonConnect [All] p1: connectstyle=Direct reliefconductorwidth=10 reliefentries=4 polygonreliefangle="90 Angle" airgapwidth=10
RoutingCorners [All] p0: scope1count=1 scope1_0_kind=Board scope1_0_value=Board scope2count=1 scope2_0_kind=Board scope2_0_value=Board commentlength=0 cornerstyle=45-Degree minsetback=100 maxsetback=100
RoutingLayers [All] p0: scope1count=1 scope1_0_kind=Board scope1_0_value=Board scope2count=1 scope2_0_kind=Board scope2_0_value=Board commentlength=0 top layer=Automatic mid layer 1=Automatic mid layer 2=Automatic mid layer 3=Automatic mid layer 4=Automatic bottom layer=Automatic
RoutingPriority [All] p0: scope1count=1 scope1_0_kind=Board scope1_0_value=Board scope2count=1 scope2_0_kind=Board scope2_0_value=Board commentlength=0
RoutingTopology [All] p0: scope1count=1 scope1_0_kind=Board scope1_0_value=Board scope2count=1 scope2_0_kind=Board scope2_0_value=Board commentlength=0 topology=Shortest
RoutingVias [All] p0: scope1count=1 scope1_0_kind=Board scope1_0_value=Board scope2count=1 scope2_0_kind=Board scope2_0_value=Board commentlength=0 holewidth=10 width=10 viastyle="Through Hole" minholewidth=10 minwidth=5 maxholewidth=40 maxwidth=65
RoutingVias ThermalPadVias [All] p0 off: scope1count=1 scope1_0_kind=Board scope1_0_value=Board scope2count=1 scope2_0_kind=Board scope2_0_value=Board commentlength=63 holewidth=7.87 width=19.68 viastyle="Through Hole" minholewidth=7.87 minwidth=19.68 maxholewidth=12.99 maxwidth=23.62 // Protel DXP Scope 1 Expression Was: IsVia and InAnyComponent
RoutingVias ThermalPadVias [IsVia and InAnyComponent] p1: holewidth=7.87 width=19.68 viastyle="Through Hole" minholewidth=7.87 minwidth=19.68 maxholewidth=12.99 maxwidth=23.62
RoutingVias [All] p2: holewidth=10 width=10 viastyle="Through Hole" minholewidth=10 minwidth=5 maxholewidth=40 maxwidth=65
ShortCircuit [All] p0: scope1count=1 scope1_0_kind=Board scope1_0_value=Board scope2count=1 scope2_0_kind=Board scope2_0_value=Board commentlength=0 allowed=FALSE
SilkToBoardRegionClearance [All] p0 off: scope1count=1 scope1_0_kind=Board scope1_0_value=Board scope2count=1 scope2_0_kind=Board scope2_0_value=Board commentlength=130 // Protel DXP Scope 1 Expression Was: Not ((IsComment or IsDesignator) And (Hide <> 'False')) and not InRegion(1000,500,4000,800)
SilkToBoardRegionClearance [Not ((IsComment or IsDesignator) And (Hide <> 'False')) and not InRegion(1000,500,4000,800)] p1:
SilkToSilkClearance [All] p0: scope1count=1 scope1_0_kind=Board scope1_0_value=Board scope2count=1 scope2_0_kind=Board scope2_0_value=Board commentlength=0
SilkToSilkClearance SilkToSilkClearance_Pb-FreeLogo [All] p0 off: scope1count=1 scope1_0_kind=Board scope1_0_value=Board scope2count=1 scope2_0_kind=Board scope2_0_value=Board commentlength=120 // Protel DXP Scope 2 Expression Was: (HasFootprint('Pb-Free_Overlay_Medium') OR HasFootprint('Pb-Free_Overlay_Small'))
SilkToSilkClearance SilkToSilkClearance_Pb-FreeLogo [(HasFootprint('Pb-Free_Overlay_Medium') OR HasFootprint('Pb-Free_Overlay_Small')) vs (HasFootprint('Pb-Free_Overlay_Medium') OR HasFootprint('Pb-Free_Overlay_Small'))] p1: silktosilkclearance=0
SilkToSilkClearance [All] p2: silktosilkclearance=2
SilkToSolderMaskClearance "Silk to Solder Mask Opening" [All] p0: scope1count=1 scope1_0_kind=Board scope1_0_value=Board scope2count=1 scope2_0_kind=Board scope2_0_value=Board commentlength=0
SilkToSolderMaskClearance SilkToComponentPadClearance [All] p0 off: scope1count=1 scope1_0_kind=Board scope1_0_value=Board scope2count=1 scope2_0_kind=Board scope2_0_value=Board commentlength=87 // Protel DXP Scope 1 Expression Was: (IsPad or IsFill or IsRegion) and InAnycomponent
SilkToSolderMaskClearance SilkToComponentPadClearance [(IsPad or IsFill or IsRegion) and InAnycomponent] p1: minsilkscreentomaskgap=5 clearancetoexposedcopper=TRUE
SilkToSolderMaskClearance "Silk to Solder Mask Opening" [All] p2: minsilkscreentomaskgap=3.94 clearancetoexposedcopper=FALSE
SolderMaskExpansion [All] p0: scope1count=1 scope1_0_kind=Board scope1_0_value=Board scope2count=1 scope2_0_kind=Board scope2_0_value=Board commentlength=0 expansion=1.97
SolderMaskExpansion [All] p1: expansion=1.97 istentingtop=FALSE
UnRoutedNet [All] p0: scope1count=1 scope1_0_kind=Board scope1_0_value=Board scope2count=1 scope2_0_kind=Board scope2_0_value=Board commentlength=0
UnRoutedNet [All] p1: checkbadconnections=TRUE
UnpouredPolygon [All] p0: scope1count=1 scope1_0_kind=Board scope1_0_value=Board scope2count=1 scope2_0_kind=Board scope2_0_value=Board commentlength=0
Width [All] p0: scope1count=1 scope1_0_kind=Board scope1_0_value=Board scope2count=1 scope2_0_kind=Board scope2_0_value=Board commentlength=0 maxlimit=100 minlimit=6 preferedwidth=8
Width [All] p1: maxlimit=100 minlimit=6 preferedwidth=8 checkconnectedcopper=TRUE
14 further rules are at their usual default settings.

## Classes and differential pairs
component class "AFE(Interal ADC)": C70 C71 C72 C73 C74 C75 C76 C77 C78 C79 C80 C81 C82 C83 C84 C85 C86 C87 C88 C89 C90 C91 C92 C93 D13 J21 J22 J23 J25 J26 J27 J28 J29 J30 J31 Q10 R140 R141 R142 R143 R144 R145 R146 R147 R148 R149 R150 R151 R152 R153 R154 R155 R156 R157 R158 R159 R160 R161 R162 R163 R164 R165 R166 R167 R168 R169 R170 R171 R172 R173 R174 R175 R176 R177 R178 R179 R180 R181 R182 R183 R184 R185 R186 R187 R188 R189 R190 R191 R192 R193 R194 R195 R196 R197 R198 R199 RT2 S2 TP37 TP38 TP39 TP40 TP41 TP42 TP43 TP44 TP45 TP46 TP47 TP48 TP49 TP50 TP51 TP52 TP53 TP54 TP55 TP56 U17 U18 U19 U20 U21 U22 U23 Y2
component class "Outputs (Internal ADC)": C94 C95 C96 C97 C98 C99 C100 C101 D14 D15 D16 D17 J32 J33 J34 Q11 R200 R201 R202 R203 R204 R205 R206 R207 R208 R209 R210 R211 R212 R213 R214 R215 R216 R217 R218 R219 R220 R221 R222 R223 R224 R225 R226 R227 R228 R229 R230 R231 R232 R233 TP57 TP58 TP59 TP60 TP61 U24 U25 U26 U27
component class "Power(Internal ADC)": C102 C103 C104 C105 C106 C107 C108 C109 C110 C111 C112 C113 C114 C115 C116 C118 C119 C120 C121 C122 C123 C124 C125 C126 C127 C128 C129 C133 C134 C135 C136 C137 D18 D19 D20 D21 D22 D23 D24 J35 J36 J37 J38 J39 J40 L2 Q12 Q14 Q15 Q17 Q18 R234 R235 R236 R237 R238 R239 R240 R241 R242 R243 R244 R245 R246 R248 R249 R250 R251 R253 R254 R255 R256 R257 R258 R259 R260 R261 R262 R263 R264 R265 R266 R267 R268 R269 R270 TP62 TP63 TP64 TP65 TP66 TP67 TP68 TP69 TP70 TP71 U28 U29 U30 U31 U33
component class Power: C42 C43 C44 C45 C46 C47 C48 C49 C50 C51 C52 C53 C54 C55 C56 C57 C58 C59 C60 C61 C62 C63 C64 C65 C66 C67 C68 C69 C117 C130 C131 C132 D6 D7 D8 D9 D10 D11 D12 J15 J16 J17 J18 J19 J20 L1 Q3 Q4 Q6 Q8 Q9 R107 R108 R109 R110 R111 R112 R113 R114 R115 R116 R117 R118 R119 R120 R121 R122 R123 R124 R125 R126 R127 R128 R129 R130 R131 R132 R133 R134 R135 R136 R137 R138 R139 R247 R252 TP27 TP28 TP29 TP30 TP31 TP32 TP33 TP34 TP35 TP36 U13 U14 U15 U16 U32
component class Outputs: C34 C35 C36 C37 C38 C39 C40 C41 D2 D3 D4 D5 J12 J13 J14 Q2 R73 R74 R75 R76 R77 R78 R79 R80 R81 R82 R83 R84 R85 R86 R87 R88 R89 R90 R91 R92 R93 R94 R95 R96 R97 R98 R99 R100 R101 R102 R103 R104 R105 R106 TP22 TP23 TP24 TP25 TP26 U9 U10 U11 U12
component class Header: J6 J16 J17 J18 J19 J20 J27 J36 J37 J38 J39 J40
component class AFE: C1 C2 C3 C4 C5 C6 C7 C8 C9 C10 C11 C12 C13 C14 C15 C16 C17 C18 C19 C20 C21 C22 C23 C24 C25 C26 C27 C28 C29 C30 C31 C32 C33 D1 J1 J2 J3 J4 J5 J6 J7 J8 J9 J10 J11 Q1 R1 R2 R3 R4 R5 R6 R7 R8 R9 R10 R11 R12 R13 R14 R15 R16 R17 R18 R19 R20 R21 R22 R23 R24 R25 R26 R27 R28 R29 R30 R31 R32 R33 R34 R35 R36 R37 R38 R39 R40 R41 R42 R43 R44 R45 R46 R47 R48 R49 R50 R51 R52 R53 R54 R55 R56 R57 R58 R59 R60 R61 R62 R63 R64 R65 R66 R67 R68 R69 R70 R71 R72 RT1 S1 TP1 TP2 TP3 TP4 TP5 TP6 TP7 TP8 TP9 TP10 TP11 TP12 TP13 TP14 TP15 TP16 TP17 TP18 TP19 TP20 TP21 U1 U2 U4 U5 U7 U8 Y1
component class "Mounting Holes": H1 H2 H3 H4 H5 H6 H7 H8
component class Logo: Logo2
component class PCB_Project_2_Hardware: FID1 FID2 FID3 FID4 FID5 FID6 FID7 FID8 FID9 FID10 FID11 FID12 H1 H2 H3 H4 H5 H6 H7 H8 H9 H10 H11 H12 H13 H14 H15 H16 H17 H18 H19 H20 LBL1 Logo1 Logo2 Logo3 Logo4 ZZ1 ZZ2 ZZ3 ZZ4
component class FiducialMark: FID1 FID2 FID3 FID4 FID5 FID6 FID7 FID8 FID9 FID10 FID11 FID12
component class AssemblyNote: ZZ1 ZZ2 ZZ3 ZZ4
component class Label: LBL1

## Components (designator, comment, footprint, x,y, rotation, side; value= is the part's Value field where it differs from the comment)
C1 "GRM2165C2A111JA01D" 0805_HV 3208.09,6922.98 r90 top
C2 "GRM2165C1H621JA01D" 0805_HV 2975.86,7113.07 r90 bottom
C3 "Capacitor" 0603 2995.58,5649.72 r90 top
C4 "Capacitor" 0603 2914,6352 r180 top
C5 "08055C104JAT2A" 0805_HV 1899.1,6900.3 r90 top
C6 "GRM32RR71H105KA01L" 1210_200 2030.13,6918.08 r90 top
C7 "GRM2165C1H621JA01D" 0805_HV 2561.53,6203.08 r90 bottom
C8 "GRM32RR71H105KA01L" 1210_200 1280.3,7006.57 r90 top
C9 "GRM1885C1H360JA01D" 0603 3283.46,7197.91 r270 top
C10 "GRM2165C1H621JA01D" 0805_HV 3470.01,7211.92 r270 top
C11 "GRM1885C1H360JA01D" 0603 2549.85,7247.62 r270 top
C12 "C1210C106K3RACTU" 1210_280 1038.94,7384.36 r90 top
C13 "CGA6P3X8R1E475K250AB" 1210_280 906.03,7385.36 r90 top
C14 "Capacitor" 0603 1015,6580.42 r0 top
C15 "GRM2165C1H621JA01D" 0805_HV 2468.02,7209.74 r90 bottom
C16 "GRM1885C1H360JA01D" 0603 2526.78,6888.35 r90 top
C17 "Capacitor" 0603 620.76,6533.18 r180 top
C18 "Capacitor" 0603 621.65,6464.67 r180 top
C19 "GRM2165C1H621JA01D" 0805_HV 2337.62,6882 r90 top
C20 "GRM2165C1H112JA01D" 0805_HV 805.65,6971.91 r0 bottom
C21 "GRM1885C1H360JA01D" 0603 2203.54,6232.75 r90 top
C22 "GRM2165C1H621JA01D" 0805_HV 2037.84,6385.88 r90 top
C23 "Capacitor" 0402 772.35,6432.55 r270 top
C24 "08055C104JAT2A" 0805_HV 3083.37,6285.7 r270 top
C25 "GRM1885C1H360JA01D" 0603 2954.06,6495.25 r270 top
C26 "Capacitor" 0402 897.87,6432.09 r270 top
C27 "GRM2165C1H621JA01D" 0805_HV 3086.16,6612.87 r0 top
C28 "GQM2195C1H330JB01D" 0805_HV 3319.46,6572.87 r180 top
C29 "GQM2195C1H330JB01D" 0805_HV 3488.69,6573.23 r180 bottom
C30 "GRM1885C1H360JA01D" 0603 2202.57,6539.72 r270 top
C31 "885012007057" 0805_HV 2181.05,7453.81 r270 top
C32 "GRM2165C1H621JA01D" 0805_HV 2074,6612 r0 bottom
C33 "Capacitor" 0603 1808,7310 r180 top
C34 "Capacitor" 0603 2363.15,5058.64 r180 top
C35 "Capacitor" 0603 3308,4460 r270 top
C36 "885012209041" FP-885012209041_1210-MFG 2978.54,5232.92 r270 top
C37 "UMK325AB7106KMHT" 1210_280 3253.48,5236.82 r90 top
C38 "GRM32RR71H105KA01L" 1210_200 3115.56,5240.13 r90 top
C39 "GRM2165C2A511JA01D" 0805_HV 2268.66,5558.04 r270 top
C40 "VJ1210Y102KXEAT5Z" 1210 1618.1,6509.54 r180 bottom
C41 "C1210C104K5RACTU" 1210 1620.27,6371.1 r180 bottom
C42 "865080443009" WCAP-ASLI_630x550 1213.44,6132.73 r90 top
C43 "GRM2165C1H621JA01D" 0805_HV 1022.97,6024.5 r90 top
C44 "GRM2165C1H122JA01D" 0805_HV 1175.84,4939.91 r180 top
C45 "GRM32DR71E106KA12L" 1210_220 1382.41,4841.8 r180 bottom
C46 "T495D226K025ATE200" 7343-31 1376.8,4874.25 r270 top
C47 "C1210C104K5RACTU" 1210 1139.58,4786.59 r270 top
C48 "08053C104JAT2A" 0805_HV 1383.77,4963.73 r180 bottom
C49 "T495X156M050ATE300" 7343-43 306.21,4891.1 r270 top
C50 "08055C105KAT2A" 0805_HV 471.41,4867.27 r270 top
C51 "GRM2165C1H122JA01D" 0805_HV 1167.82,5459.05 r180 top
C52 "T495D226K025ATE200" 7343-31 1368.52,5391.41 r270 top
C53 "C1210C104K5RACTU" 1210 1152.15,5304.35 r270 top
C54 "GRM32DR71E106KA12L" 1210_220 1383.13,5364.97 r180 bottom
C55 "08053C104JAT2A" 0805_HV 1384.48,5486.89 r180 bottom
C56 "UMK325AB7106KMHT" 1210_280 355.58,5394.09 r270 top
C57 "08055C105KAT2A" 0805_HV 477.21,5396.87 r270 top
C58 "UMK325AB7106KMHT" 1210_280 352.54,5937.71 r270 top
C59 "08055C105KAT2A" 0805_HV 463.27,5959.55 r270 top
C60 "08055C105KAT2A" 0805_HV 1844.04,5854 r0 bottom
C61 "C0805C124K5RACTU" 0805_HV 1147.32,4425.23 r270 bottom
C62 "08055C105KAT2A" 0805_HV 1844.04,5207.77 r180 bottom
C63 "GRM2165C1H122JA01D" 0805_HV 2234,4395 r180 top
C64 "T495D226K025ATE200" 7343-31 2426.77,4338.69 r270 top
C65 "C1210C104K5RACTU" 1210 2226.28,4248.94 r270 top
C66 "GRM32DR71E106KA12L" 1210_220 2457.26,4309.56 r180 bottom
C67 "08053C104JAT2A" 0805_HV 2458.61,4431.48 r180 bottom
C68 "T495X156M050ATE300" 7343-43 1397.53,4324.12 r270 top
C69 "08055C105KAT2A" 0805_HV 1553.78,4334.34 r270 top
C70 "GRM2165C2A111JA01D" 0805L 3217.4,2979.86 r90 top
C71 "GRM2165C2A511JA01D" 0805_HV 2971.92,3162.09 r90 bottom
C72 "Capacitor" 0603L 2898.26,2396.98 r180 top
C73 "GRM2165C2A511JA01D" 0805L 2564,2254 r90 bottom
C74 "GRM2165C2A511JA01D" 0805_HV 3374.38,3243.55 r270 top
C75 "C1210C106K3RACTU" 1210_280 924.47,3527.31 r180 top
C76 "CGA6P3X8R1E475K250AB" 1210_280 925.76,3402 r180 top
C77 "Capacitor" 0603 1024.72,2597.35 r0 top
C78 "GRM2165C2A511JA01D" 0805_HV 2502.51,3299.29 r270 top
C79 "Capacitor" 0603 620.76,2583.18 r180 top
C80 "Capacitor" 0603 621.65,2514.67 r180 top
C81 "GRM2165C2A511JA01D" 0805_HV 2502.81,2908.54 r90 top
C82 "Capacitor" 0603 3002.19,1749.11 r270 top
C83 "GRM2165C1H112JA01D" 0805_HV 805.65,3021.91 r0 bottom
C84 "GRM2165C2A511JA01D" 0805_HV 2180,2258 r90 top
C85 "Capacitor" 0402 772.35,2482.55 r270 top
C86 "Capacitor" 0402 897.87,2482.09 r270 top
C87 "08055C104JAT2A" 0805_HV 3075.12,2332.86 r270 top
C88 "GRM2165C2A511JA01D" 0805_HV 2900.17,2552.01 r270 bottom
C89 "GQM2195C1H330JB01D" 0805_HV 3315.91,2606.93 r180 top
C90 "GQM2195C1H330JB01D" 0805_HV 3480,2605 r180 bottom
C91 "885012007057" 0805_HV 2181.05,3503.81 r270 top
C92 "Capacitor" 0603 1808,3360 r180 top
C93 "GRM2165C2A511JA01D" 0805_HV 2166.47,2594.44 r270 top
C94 "Capacitor" 0603 2363.02,1101.13 r180 top
C95 "885012209041" FP-885012209041_1210-MFG 2975.28,1275.49 r270 top
C96 "UMK325AB7106KMHT" 1210_280 3250.22,1279.4 r90 top
C97 "GRM32RR71H105KA01L" 1210_200 3112.3,1282.7 r90 top
C98 "Capacitor" 0603 3308,510 r270 top
C99 "GRM2165C2A511JA01D" 0805_HV 2262.66,1588.04 r270 top
C100 "VJ1210Y102KXEAT5Z" 1210 1620.61,2406.98 r180 bottom
C101 "C1210C104K5RACTU" 1210 1621.1,2543.77 r180 bottom
C102 "865080443009" WCAP-ASLI_630x550 1213.44,2182.73 r90 top
C103 "GRM2165C1H621JA01D" 0805_HV 1019.7,2074.52 r90 top
C104 "GRM2165C1H122JA01D" 0805_HV 1163.26,981.93 r180 top
C105 "T495D226K025ATE200" 7343-31 1353.96,908.44 r270 top
C106 "C1210C104K5RACTU" 1210 1139.58,836.59 r270 top
C107 "GRM32DR71E106KA12L" 1210_220 1378.24,874.77 r180 bottom
C108 "08053C104JAT2A" 0805_HV 1383.77,1013.73 r180 bottom
C109 "T495X156M050ATE300" 7343-43 306.75,951.16 r270 top
C110 "08055C105KAT2A" 0805_HV 468.3,918.32 r270 top
C111 "GRM2165C1H122JA01D" 0805_HV 1167.82,1509.05 r180 top
C112 "T495D226K025ATE200" 7343-31 1352.64,1444.09 r270 top
C113 "C1210C104K5RACTU" 1210 1152.15,1354.35 r270 top
C114 "GRM32DR71E106KA12L" 1210_220 1383.13,1414.97 r180 bottom
C115 "08053C104JAT2A" 0805_HV 1384.48,1536.89 r180 bottom
C116 "08055C105KAT2A" 0805_HV 1844.04,1904 r0 bottom
C117 "C0603C104J3RACTU" 0603 420.72,4244.17 r270 top
C118 "UMK325AB7106KMHT" 1210_280 346.76,1988.14 r270 top
C119 "08055C105KAT2A" 0805_HV 455.86,2009.52 r270 top
C120 "UMK325AB7106KMHT" 1210_280 368,1424.04 r270 top
C121 "08055C105KAT2A" 0805_HV 475.97,1450.41 r270 top
C122 "08055C105KAT2A" 0805_HV 1844.04,1344.26 r180 bottom
C123 "GRM2165C1H122JA01D" 0805_HV 2249.59,452.23 r180 top
C124 "T495D226K025ATE200" 7343-31 2426.83,388.69 r270 top
C125 "C1210C104K5RACTU" 1210 2226.34,298.94 r270 top
C126 "GRM32DR71E106KA12L" 1210_220 2457.32,359.56 r180 bottom
C127 "08053C104JAT2A" 0805_HV 2457,470 r180 bottom
C128 "T495X156M050ATE300" 7343-43 1411.36,362.83 r270 top
C129 "08055C105KAT2A" 0805_HV 1552.4,384.68 r270 top
C130 "12065A202JAT2A" 1206 1200.87,4388.38 r0 top
C131 "12065A202JAT2A" 1206 1192.8,4185 r0 top
C132 "C0603C104J3RACTU" 0603 420.72,4406 r90 top
C133 "C0805C124K5RACTU" 0805_HV 1147.06,474.78 r270 bottom
C134 "C0603C104J3RACTU" 0603 420.46,293.72 r270 top
C135 "12065A202JAT2A" 1206 1200.61,437.92 r0 top
C136 "12065A202JAT2A" 1206 1192.54,234.55 r0 top
C137 "C0603C104J3RACTU" 0603 420.46,455.55 r90 top
D1 "SML-LXF0805SRC-TR" Lumex_SML-LXF0805SRC_RED 1178,7394 r90 top
D2 "SML-LXF0805SRC-TR" Lumex_SML-LXF0805SRC_RED 3017.09,4139.45 r90 top
D3 "SML-LXF0805SRC-TR" Lumex_SML-LXF0805SRC_RED 2894.38,4139.45 r90 top
D4 "SML-LXF0805SRC-TR" Lumex_SML-LXF0805SRC_RED 2773.24,4139.45 r90 top
D5 "SML-LXF0805SRC-TR" Lumex_SML-LXF0805SRC_RED 2649.99,4139.45 r90 top
D6 "1N6642UD1" ST_LCC-2D 1116.21,5015.88 r90 bottom
D7 "1N6642UD1" ST_LCC-2D 1116.21,4785.58 r90 bottom
D8 "SS1P3L-M3/84A" DO-220AA 614.22,5765.28 r0 top
D9 "1N6642UD1" ST_LCC-2D 1116.93,5539.04 r90 bottom
D10 "1N6642UD1" ST_LCC-2D 1116.93,5308.75 r90 bottom
D11 "1N6642UD1" ST_LCC-2D 2191.06,4483.64 r90 bottom
D12 "1N6642UD1" ST_LCC-2D 2191.06,4253.34 r90 bottom
D13 "SML-LXF0805SRC-TR" Lumex_SML-LXF0805SRC_RED 1178,3444 r90 top
D14 "SML-LXF0805SRC-TR" Lumex_SML-LXF0805SRC_RED 3017.09,189.45 r90 top
D15 "SML-LXF0805SRC-TR" Lumex_SML-LXF0805SRC_RED 2894.38,189.45 r90 top
D16 "SML-LXF0805SRC-TR" Lumex_SML-LXF0805SRC_RED 2773.24,189.45 r90 top
D17 "SML-LXF0805SRC-TR" Lumex_SML-LXF0805SRC_RED 2649.99,189.45 r90 top
D18 "1N6642UD1" ST_LCC-2D 1116.21,1065.88 r90 bottom
D19 "1N6642UD1" ST_LCC-2D 1116.21,835.59 r90 bottom
D20 "SS1P3L-M3/84A" DO-220AA 603.62,1820.66 r0 top
D21 "1N6642UD1" ST_LCC-2D 1116.93,1589.04 r90 bottom
D22 "1N6642UD1" ST_LCC-2D 1116.93,1358.75 r90 bottom
D23 "1N6642UD1" ST_LCC-2D 2191.12,533.64 r90 bottom
D24 "1N6642UD1" ST_LCC-2D 2191.12,303.34 r90 bottom
FID1 "Fiducial" Fiducial10-20 464.43,7680 r0 top
FID2 "Fiducial" Fiducial10-20 464.43,4060 r90 top
FID3 "Fiducial" Fiducial10-20 3017.14,7680 r0 top
FID4 "Fiducial" Fiducial10-20 464.02,7679.58 r90 bottom
FID5 "Fiducial" Fiducial10-20 3016.44,7679.78 r90 bottom
FID6 "Fiducial" Fiducial10-20 464.03,4059.73 r90 bottom
FID7 "Fiducial" Fiducial10-20 464.43,3730.05 r90 top
FID8 "Fiducial" Fiducial10-20 3017.14,3730.05 r90 top
FID9 "Fiducial" Fiducial10-20 464.43,113.9 r90 top
FID10 "Fiducial" Fiducial10-20 464.03,3729.91 r90 bottom
FID11 "Fiducial" Fiducial10-20 3017.17,3729.9 r90 bottom
FID12 "Fiducial" Fiducial10-20 464.02,113.84 r90 bottom
H1 "NY PMS 440 0025 PH" "NY PMS 440 0025 PH" 200,7600 r0 top locked
H2 "NY PMS 440 0025 PH" "NY PMS 440 0025 PH" 3279,7600 r0 top locked
H3 "NY PMS 440 0025 PH" "NY PMS 440 0025 PH" 200,4144.49 r0 top locked
H4 "NY PMS 440 0025 PH" "NY PMS 440 0025 PH" 3279,4145 r0 top locked
H5 "NY PMS 440 0025 PH" "NY PMS 440 0025 PH" 200,3648.11 r0 top locked
H6 "NY PMS 440 0025 PH" "NY PMS 440 0025 PH" 3279,3648.11 r0 top locked
H7 "NY PMS 440 0025 PH" "NY PMS 440 0025 PH" 200,201.02 r0 top locked
H8 "NY PMS 440 0025 PH" "NY PMS 440 0025 PH" 3279,201.02 r0 top
H9 "SJ-5303 (CLEAR)" Bumpon_SJ5003Transparent 8135,547 r180 bottom
H10 "SJ-5303 (CLEAR)" Bumpon_SJ5003Transparent 8135,1089 r180 bottom
H11 "SJ-5303 (CLEAR)" Bumpon_SJ5003Transparent 8124,-49 r180 bottom
H12 "SJ-5303 (CLEAR)" Bumpon_SJ5003Transparent 8135,1642 r180 bottom
H13 "1902C" Keystone_1902C 200,7600 r180 bottom locked
H14 "1902C" Keystone_1902C 3279,7600 r180 bottom locked
H15 "1902C" Keystone_1902C 200,4144.49 r180 bottom
H16 "1902C" Keystone_1902C 3279,4145 r180 bottom locked
H17 "1902C" Keystone_1902C 200,3648.11 r180 bottom
H18 "1902C" Keystone_1902C 3279,3648.11 r180 bottom
H19 "1902C" Keystone_1902C 200,201.02 r180 bottom
H20 "1902C" Keystone_1902C 3279,201.02 r180 bottom
J1 "ED555/2DS" TERM_BLK_ED555-2DS 3735,6894.45 r90 top
J2 "ED555/2DS" TERM_BLK_ED555-2DS 3735,5970.45 r90 top
J3 "ED555/2DS" TERM_BLK_ED555-2DS 3735,7202.45 r90 top
J4 "ED555/2DS" TERM_BLK_ED555-2DS 3735,6586.45 r90 top
J5 "ED555/2DS" TERM_BLK_ED555-2DS 3735,6278.45 r90 top
J6 "Header_7x2" 3M_x2514-60xx 200,6771.53 r270 top
J7 "ED555/2DS" TERM_BLK_ED555-2DS 3738,5354.45 r90 top
J8 "ED555/2DS" TERM_BLK_ED555-2DS 3735,5662.45 r90 top
J9 "ED555/2DS" TERM_BLK_ED555-2DS 3739,5046.45 r90 top
J10 "ED555/2DS" TERM_BLK_ED555-2DS 3735,7510.45 r90 top
J12 "ED555/2DS" TERM_BLK_ED555-2DS 3738,4122.45 r90 top
J13 "ED555/2DS" TERM_BLK_ED555-2DS 3738,4738.45 r90 top
J14 "ED555/2DS" TERM_BLK_ED555-2DS 3738,4430.45 r90 top
J15 "ED555/4DS" TERM_BLK_ED555-4DS 170,6067.09 r270 top
J16 "TSW-102-07-T-S" Samtec_TSW-102-07-T-S 1558,5044 r270 top
J17 "TSW-103-07-T-S" Samtec_TSW-103-07-T-S 573.48,5109.78 r180 top
J18 "TSW-102-07-T-S" Samtec_TSW-102-07-T-S 1545.77,5549.01 r270 top
J19 "TSW-103-07-T-S" Samtec_TSW-103-07-T-S 573.48,5617.78 r180 top
J20 "TSW-102-07-T-S" Samtec_TSW-102-07-T-S 2372.35,4725.12 r0 top
J21 "ED555/2DS" TERM_BLK_ED555-2DS 3735,2935.1 r90 top
J22 "ED555/2DS" TERM_BLK_ED555-2DS 3735,2011.1 r90 top
J23 "ED555/2DS" TERM_BLK_ED555-2DS 3735,3243.1 r90 top
J25 "ED555/2DS" TERM_BLK_ED555-2DS 3735,2627.1 r90 top
J26 "ED555/2DS" TERM_BLK_ED555-2DS 3735,2319.1 r90 top
J27 "Header_7x2" 3M_x2514-60xx 200,2821.53 r270 top
J28 "ED555/2DS" TERM_BLK_ED555-2DS 3735,1394.93 r90 top
J29 "ED555/2DS" TERM_BLK_ED555-2DS 3735,1703.1 r90 top
J30 "ED555/2DS" TERM_BLK_ED555-2DS 3735,1086.91 r90 top
J31 "ED555/2DS" TERM_BLK_ED555-2DS 3735,3551.1 r90 top
J32 "ED555/2DS" TERM_BLK_ED555-2DS 3737,167 r90 top
J33 "ED555/2DS" TERM_BLK_ED555-2DS 3735,781.91 r90 top
J34 "ED555/2DS" TERM_BLK_ED555-2DS 3735,473.51 r90 top
J35 "ED555/4DS" TERM_BLK_ED555-4DS 170,2117.09 r270 top
J36 "TSW-102-07-T-S" Samtec_TSW-102-07-T-S 1555.11,1083.46 r270 top
J37 "TSW-103-07-T-S" Samtec_TSW-103-07-T-S 572.38,1162.5 r180 top
J38 "TSW-102-07-T-S" Samtec_TSW-102-07-T-S 1546.51,1606.14 r270 top
J39 "TSW-103-07-T-S" Samtec_TSW-103-07-T-S 572.38,1665.5 r180 top
J40 "TSW-102-07-T-S" Samtec_TSW-102-07-T-S 2374.56,766 r0 top
L1 "150 uH 7447773151" FP-7447773151_SMT_IND_7MM4_7MM3-MFG 671.97,6019.7 r0 top
L2 "150 uF  7447773151" FP-7447773151_SMT_IND_7MM4_7MM3-MFG 672.9,2073.34 r0 top
LBL1 "THT-14-423-10" Label_650x200 1798.28,788.25 r0 top
Logo1 "CE Mark" CE_Mark_5mm 1742.42,4689.28 r0 top
Logo2 "Texas Instruments" TI_Stacked_Overlay_Small 1854.19,3098.34 r0 top
Logo3 "FCC disclaimer" FCC_disclaimer 2340.16,2996.14 r0 top locked
Logo4 "WEEE logo" WEEE_Minimum 2108.32,5100.86 r0 top
Q1 "MMBT3904LT1G" SOT-23 2325.03,7455.45 r180 top
Q2 "CSD18541F5" YJK0003A 2855.63,4951.67 r270 top
Q3 "CSD16301Q2" DQK0006C 756.34,5773.82 r90 top
Q4 "MMBT2907AT-7-F" SOT-523 1850.94,5801.28 r0 top
Q6 "MMBT3904T-7-F" SOT-523 1850.94,5591.95 r0 top
Q8 "MMBT2907AT-7-F" SOT-523 1850.94,5466.02 r0 top
Q9 "MMBT3904T-7-F" SOT-523 1850.94,5236.31 r0 top
Q10 "MMBT3904LT1G" SOT-23 2325.03,3505.45 r180 top
Q11 "CSD18541F5" YJK0003A 2856.51,1001.88 r270 top
Q12 "MMBT2907AT-7-F" SOT-523 1850.94,1851.28 r0 top
Q14 "CSD16301Q2" DQK0006C 749.49,1820.82 r90 top
Q15 "MMBT3904T-7-F" SOT-523 1850.94,1641.95 r0 top
Q17 "MMBT2907AT-7-F" SOT-523 1850.94,1516.02 r0 top
Q18 "MMBT3904T-7-F" SOT-523 1850.94,1286.31 r0 top
R1 "ERJ-6ENF9531V" 0805_HV 3302,6923 r270 top
R2 "5106" 5106 3242,6797.17 r0 top
R3 "RT0805BRD072K46L" 0805_HV 3100.33,7116.04 r90 bottom
R4 "5106" 5106 2565,6999.23 r0 top
R5 "5106" 5106 2565,7085 r180 top
R6 "5106" 5106 3102.56,6927.08 r90 bottom
R7 "5106" 5106 2269.39,5719.99 r270 top
R8 "5106" 5106 2373.79,5720.73 r90 top
R9 "ERJ-6GEYJ104V" 0805_HV 2882.73,5588.47 r270 bottom
R10 "RT0805BRD0789R8L" 0805_HV 2977.02,6941.08 r90 bottom
R11 "RT0805BRD072K55L" 0805_HV 3254.02,6883.89 r0 bottom
R12 "ERJ-6GEYJ104V" 0805_HV 3002.19,5587.72 r90 bottom
R13 "RT0805BRD0710K2L" 0805_HV 3254.02,6977.8 r180 bottom
R14 "RT0805BRD0732K4L" 0805_HV 2771.93,6440.46 r90 bottom
R15 "RT0805BRD0732K4L" 0805_HV 2678,6439.28 r270 bottom
R16 "RT0805BRD071K3L" 0805_HV 2812.63,6298.77 r180 bottom
R17 "RT0805BRD0776R8L" 0805_HV 2652.11,6202.53 r270 bottom
R18 "RLP73N3AR082FTDF" 2512 3049.29,6236.65 r90 bottom
R19 "RT0805BRD071K3L" 0805_HV 2815.47,6201.45 r180 bottom
R20 "5106" 5106 2233.61,6428.67 r180 top
R21 "ERJ-6ENF1002V" 0805_HV 3374.11,7212.68 r90 top
R22 "5106" 5106 2233.61,6342.56 r0 top
R23 "RT0805BRD0716K2L" 0805_HV 2891.06,6230.45 r270 top
R24 "RT0805BRD071M2L" 0805_HV 3252.38,7252.3 r180 bottom
R25 "ERJ-3GEY0R00V" 0603 3193.74,7197.91 r90 top
R26 "RN73C2A100KBTD" RN73_2A 3253.11,7068.45 r0 top
R27 "5106" 5106 3243.05,7161.33 r0 bottom
R28 "RT0805BRD0785R6L" 0805_HV 3241.9,7311.35 r0 top
R29 "ERJ-6ENF1002V" 0805_HV 2436.83,7177.29 r180 top
R30 "RT0805BRD0732K4L" 0805_HV 3253.11,7068.39 r180 bottom
R31 "ERJ-3GEY0R00V" 0603 2617.96,7247.62 r90 top
R32 "CRCW0805200RFKEA" 0805_HV 1100.89,7221.91 r0 top
R33 "RT0805BRD076K98L" 0805_HV 2577,7208.11 r90 bottom
R34 "RT0805BRD0785R6L" 0805_HV 2436.83,7269.1 r180 top
R35 "Resistor" 1210M 3493.9,6861.5 r0 top
R36 "ERJ-6ENF1002V" 0805_HV 2433.3,6881.58 r270 top
R37 "Resistor" 1210M 3493.9,6705.9 r0 top
R38 "ERJ-3GEY0R00V" 0603 2602.64,6890.04 r270 top
R39 "CRCW080510K0FKEA" 0805_HV 548.45,6765.69 r90 bottom
R40 "RG2012P-3832-B-T5" 0805_HV 2711.01,7114.43 r270 bottom
R41 "CRCW080510K0FKEA" 0805_HV 550.48,6599.74 r270 bottom
R42 "5106" 5106 2845.81,7113.07 r90 bottom
R43 "RT0805BRD0785R6L" 0805_HV 2561.32,6771.52 r180 top
R44 "RG2012P-4022-B-T5" 0805_HV 2845.81,6947.8 r90 bottom
R45 "RT0805BRD07965KL" 0805_HV 2710.34,6948.48 r90 bottom
R46 "ERJ-6GEYJ473V" 0805_HV 641.05,6969.88 r180 bottom
R47 "ERJ-6ENF1002V" 0805_HV 2074.7,6262.41 r180 top
R48 "RT0805BRD07597KL" 0805_HV 2167.2,6209 r270 bottom
R49 "ERJ-3GEY0R00V" 0603 2273.99,6231.74 r270 top
R50 "RT0805BRD07100KL" 0805_HV 2469.7,6203.63 r270 bottom
R51 "5106" 5106 2264.09,6202.95 r270 bottom
R52 "RT0805BRD0785R6L" 0805_HV 2073.49,6163.66 r180 top
R53 "RT0805BRD0714KL" 0805_HV 2377.62,6203.62 r90 bottom
R54 "ERJ-6ENF1002V" 0805_HV 3078.79,6487.1 r90 top
R55 "ERJ-3GEY0R00V" 0603 2883.08,6495.25 r90 top
R56 "MCR25JZHFLR240" 1210 3377.96,6149.66 r180 top
R57 "RT0805BRD0785R6L" 0805_HV 2926,6612 r0 top
R58 "5106" 5106 3486.29,6573.23 r0 top
R59 "ERJ-6ENF1002V" 0805_HV 2072,6521.45 r180 top
R60 "CRCW080510K0FKEA" 0805_HV 1259,7391 r270 top
R61 "CRCW080510K0FKEA" 0805_HV 1827,7487 r270 bottom
R62 "ERJ-6GEYJ152V" 0805_HV 1218.88,7520.09 r0 top
R63 "RT0805BRD07481KL" 0805_HV 2167.2,6430.59 r90 bottom
R64 "ERJ-3GEY0R00V" 0603 2271.46,6539.72 r90 top
R65 "RG2012P-103-B-T5" 0805_HV 2468.59,6431.83 r270 bottom
R66 "RMCF0603ZT0R00" 0603 2028.05,7494.42 r180 top
R67 "5106" 5106 2262.47,6432.79 r270 bottom
R68 "RT0805BRD0785R6L" 0805_HV 2072,6621.51 r180 top
R69 "RMCF0603ZT0R00" 0603 2028.05,7404.91 r180 top
R70 "RT0805BRD07481KL" 0805_HV 2377.36,6430.86 r90 bottom
R71 "RMCF0603ZT0R00" 0603 2027.7,7494.1 r180 bottom
R72 "RMCF0603ZT0R00" 0603 2028.39,7404.9 r180 bottom
R73 "ERJ-6GEYJ104V" 0805_HV 2288.95,5198.83 r90 top
R74 "ERJ-6GEYJ104V" 0805_HV 2383.4,5197.15 r270 top
R75 "ERJ-6GEYJ101V" 0805_HV 3368.41,5210.84 r270 top
R76 "ERJ-6GEYJ102V" 0805_HV 3186.52,5091.09 r180 top
R77 "CRCW080510K0JNEA" 0805_HV 3018.19,5090.66 r180 top
R78 "ERJ-6GEYJ102V" 0805_HV 3017.09,4134.79 r90 bottom
R79 "ERJ-6ENF1372V" 0805_HV 3433,4676 r90 top
R80 "RT0805BRD07750RL" 0805_HV 2731.23,4952.57 r0 top
R81 "ERJ-6ENF1502V" 0805_HV 3086,4844 r180 top
R82 "5106" 5106 2767.63,5565.7 r270 bottom
R83 "ERJ-6GEYJ102V" 0805_HV 2467.66,5561.88 r270 bottom
R84 "RT0805BRD0711K5L" 0805_HV 2673.63,5562.97 r270 bottom
R85 "CRCW080510K0FKEA" 0805_HV 3257.25,4844 r180 top
R86 "ERJ-6ENF1001V" 0805_HV 3332.42,4676 r270 top
R87 "CRCW0805442RFKEA" 0805_HV 2373.79,5559.5 r90 top
R88 "ERJ-6GEYJ102V" 0805_HV 2374.52,5563.17 r90 bottom
R89 "RT0805BRD0735K7L" 0805_HV 2580.38,5564.07 r90 bottom
R90 "ERJ-6GEYJ102V" 0805_HV 2894.38,4134.79 r90 bottom
R91 "ERJ-6ENF1372V" 0805_HV 3495,4474 r270 top
R92 "RR1220P-202-D" 0805_HV 3403,4474.5 r90 top
R93 "ERJ-6GEYJ102V" 0805_HV 2773.24,4134.79 r90 bottom
R94 "CRCW080510K7FKEA" 0805_HV 2656.04,4765.81 r90 top
R95 "ERJ-6GEYJ103V" 0805_HV 2945.5,5981.99 r180 bottom
R96 "ERJ-6GEYJ102V" 0805_HV 2898.12,5838 r270 bottom
R97 "RT0805BRD07626RL" 0805_HV 3000.73,5838.47 r90 top
R98 "CRCW080514K7FKEA" 0805_HV 2751.35,4766 r270 top
R99 "ERJ-6GEYJ104V" 0805_HV 3000.73,5838 r270 bottom
R100 "ERJ-6GEYJ102V" 0805_HV 2648.42,4134.79 r90 bottom
R101 "ERJ-6ENF1102V" 0805_HV 2655.24,4584.57 r270 top
R102 "5106" 5106 2373.79,5858.84 r90 top
R103 "5106" 5106 2374.52,5858.84 r270 bottom
R104 "CRCW080510K0FKEA" 0805_HV 2751.35,4584.57 r90 top
R105 "5106" 5106 2272,5864.12 r270 top
R106 "5106" 5106 1888.92,6581.12 r270 top
R107 "5106" 5106 1435.52,5783.17 r90 top
R108 "5106" 5106 1538.1,5782.84 r90 top
R109 "RG2012P-102-B-T5" 0805_HV 1217.61,5886.66 r0 top
R110 "5106" 5106 1067.39,5887.18 r180 top
R111 "RC0603FR-0749R9L" 0603 1213.44,5049.99 r270 top
R112 "RC1206FR-073K9L" 1206 1124,5083 r90 top
R113 "5106" 5106 1007.16,4900.73 r90 bottom
R114 "5106" 5106 1230.01,4893.96 r90 bottom
R115 "5106" 5106 1231.36,4751.72 r270 bottom
R116 "RG2012P-222-B-T5" 0805_HV 1230.01,5052.46 r90 bottom
R117 "RC0603FR-0749R9L" 0603 1209.85,5572.27 r270 top
R118 "RG2012P-4021-B-T5" 0805_HV 1127.05,5586.51 r90 top
R119 "5106" 5106 1007.88,5423.9 r90 bottom
R120 "5106" 5106 1230.72,5417.12 r90 bottom
R121 "5106" 5106 861.69,5790.13 r90 top
R122 "5106" 5106 1232.08,5274.88 r270 bottom
R123 "RT0805BRD07459RL" 0805_HV 1230.72,5575.62 r90 bottom
R124 "ERJ-6GEYJ304V" 0805_HV 1844.04,5763 r180 bottom
R125 "RN73C2A100KBTD" RN73_2A 520.02,4233.09 r270 bottom
R126 "ERJ-6GEYJ302V" 0805_HV 1844.59,5702.65 r0 top
R127 "CRCW080510K7FKEA" 0805_HV 413.58,4233.09 r90 bottom
R128 "ERJ-6GEYJ203V" 0805_HV 1844.04,5577.66 r0 bottom
R129 "ERJ-6GEYJ203V" 0805_HV 320.9,4417.45 r270 bottom
R130 "ERJ-6GEYJ203V" 0805_HV 1844.04,5485 r0 bottom
R131 "ERJ-6GEYJ203V" 0805_HV 414.17,4417.4 r270 bottom
R132 "ERJ-6GEYJ302V" 0805_HV 1849.79,5352.05 r0 top
R133 "ERJ-6GEYJ304V" 0805_HV 1844.04,5294.26 r0 bottom
R134 "RC0603FR-0749R9L" 0603 2283,4508 r270 top
R135 "RC1206FR-073K9L" 1206 2195,4543 r90 top
R136 "5106" 5106 2082.01,4368.49 r90 bottom
R137 "5106" 5106 2304.85,4361.72 r90 bottom
R138 "5106" 5106 2306.21,4219.47 r270 bottom
R139 "RG2012P-222-B-T5" 0805_HV 2304.85,4520.22 r90 bottom
R140 "RT0805BRD074K81L" 0805_HV 3304.76,2973.33 r270 top
R141 "5106" 5106 3238,2849 r0 top
R142 "RT0805BRD071K23L" 0805_HV 3096.39,3165.05 r90 bottom
R143 "5106" 5106 2562,3131 r0 top
R144 "5106" 5106 2562,3041 r180 top
R145 "5106" 5106 3098.62,2976.1 r90 bottom
R146 "CRCW0805442RFKEA" 0805_HV 2973.08,2990.1 r90 bottom
R147 "ERJ-6GEYJ104V" 0805_HV 2882.73,1638.47 r270 bottom
R148 "RT0805BRD072K55L" 0805_HV 3256.1,2908.04 r0 bottom
R149 "RT0805BRD0710K2L" 0805_HV 3256.1,2998.64 r180 bottom
R150 "ERJ-6GEYJ104V" 0805_HV 3004.67,1636.24 r90 bottom
R151 "RG2012P-1542-B-T5" 0805_HV 2679,2487 r90 bottom
R152 "RT0805BRD0716K4L" 0805_HV 2773,2487 r270 bottom
R153 "RT0805BRD071K3L" 0805_HV 2811.63,2355.77 r180 bottom
R154 "CRCW0805442RFKEA" 0805_HV 2647,2273.66 r270 bottom
R155 "RLP73N3AR082FTDF" 2512 3028.89,2300.36 r90 bottom
R156 "RT0805BRD071K3L" 0805_HV 2814.06,2260.5 r180 bottom
R157 "5106" 5106 2210.11,2471.4 r0 top
R158 "5106" 5106 2210.11,2381.39 r180 top
R159 "RT0805BRD078K16L" 0805_HV 2887.51,2279.51 r270 top
R160 "RT0805BRD07887KL" 0805_HV 3256.69,3295.17 r180 bottom
R161 "RG2012P-3013-B-T5" 0805_HV 3259,3109 r0 top
R162 "5106" 5106 3250.61,3204.04 r0 bottom
R163 "CRCW0805442RFKEA" 0805_HV 3240.71,3276.27 r0 top
R164 "RT0805BRD0742K2L" 0805_HV 3261,3110 r180 bottom
R165 "CRCW0805200RFKEA" 0805_HV 1031.5,3264.88 r0 top
R166 "RT0805BRD076K98L" 0805_HV 2562,3268 r180 bottom
R167 "CRCW0805442RFKEA" 0805_HV 2596.66,3300.69 r90 top
R168 "Resistor" 1210M 3481,2895 r0 top
R169 "Resistor" 1210M 3482,2737 r0 top
R170 "CRCW080510K0FKEA" 0805_HV 543.68,2815.83 r90 bottom
R171 "RT0805BRD07229KL" 0805_HV 2707.08,3163.44 r270 bottom
R172 "CRCW080510K0FKEA" 0805_HV 544.75,2650.7 r270 bottom
R173 "5106" 5106 2342.49,1714.98 r0 top
R174 "5106" 5106 2342.49,1801.59 r180 top
R175 "5106" 5106 2841.87,3162.09 r90 bottom
R176 "CRCW0805442RFKEA" 0805_HV 2596.96,2908.54 r270 top
R177 "RG2012P-4993-B-T5" 0805_HV 2841.87,2996.82 r90 bottom
R178 "RT0805BRD07459KL" 0805_HV 2706.4,2997.5 r90 bottom
R179 "ERJ-6GEYJ473V" 0805_HV 641.06,3019.88 r180 bottom
R180 "RT0805BRD07898KL" 0805_HV 2180,2269.19 r90 bottom
R181 "RT0805BRD07665KL" 0805_HV 2466.15,2252.69 r270 bottom
R182 "5106" 5106 2275,2260.93 r270 bottom
R183 "CRCW0805442RFKEA" 0805_HV 2275.06,2259.01 r270 top
R184 "RT0805BRD0743K2L" 0805_HV 2378.87,2254.07 r90 bottom
R185 "Y14870R10000B9W" CSM2512_T3 3375,2149.1 r0 top
R186 "CRCW0805442RFKEA" 0805_HV 2900.17,2551.28 r90 top
R187 "5106" 5106 3474,2606.93 r0 top
R188 "CRCW080510K0FKEA" 0805_HV 1259,3441 r270 top
R189 "CRCW080510K0FKEA" 0805_HV 1827,3537 r270 bottom
R190 "ERJ-6GEYJ152V" 0805_HV 1218.88,3570.09 r0 top
R191 "RMCF0603ZT0R00" 0603 2022.39,3543.16 r180 top
R192 "RT0805BRD071M2L" 0805_HV 2156,2482 r90 bottom
R193 "RMCF0603ZT0R00" 0603 2020,3464.66 r180 top
R194 "RN73C2A100KBTD" RN73_2A 2464.85,2480.17 r270 bottom
R195 "5106" 5106 2254,2477.5 r270 bottom
R196 "CRCW0805442RFKEA" 0805_HV 2261,2594.58 r90 top
R197 "RMCF0603ZT0R00" 0603 2021.1,3550.49 r180 bottom
R198 "RT0805BRD0796K5L" 0805_HV 2373.81,2479.93 r90 bottom
R199 "RMCF0603ZT0R00" 0603 2018.52,3464.71 r180 bottom
R200 "ERJ-6GEYJ104V" 0805_HV 2290.16,1250.2 r90 top
R201 "ERJ-6GEYJ104V" 0805_HV 2384.58,1249.25 r270 top
R202 "ERJ-6GEYJ101V" 0805_HV 3367.82,1258.71 r270 top
R203 "ERJ-6GEYJ102V" 0805_HV 3170.78,1130.06 r180 top
R204 "CRCW080510K0JNEA" 0805_HV 3009.81,1129.86 r180 top
R205 "RT0805BRD07750RL" 0805_HV 2708.15,1001.88 r0 top
R206 "5106" 5106 2764.02,1617.2 r270 bottom
R207 "ERJ-6GEYJ102V" 0805_HV 2477.56,1616.35 r270 bottom
R208 "RT0805BRD0711K5L" 0805_HV 2669.49,1612.8 r90 bottom
R209 "CRCW0805442RFKEA" 0805_HV 2363.79,1589.5 r90 top
R210 "ERJ-6GEYJ102V" 0805_HV 3017.09,184.79 r90 bottom
R211 "ERJ-6GEYJ102V" 0805_HV 2363.79,1615.09 r90 bottom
